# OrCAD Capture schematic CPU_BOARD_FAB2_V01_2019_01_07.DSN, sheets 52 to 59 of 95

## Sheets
52 032 BDX-DE POWER_2: size B
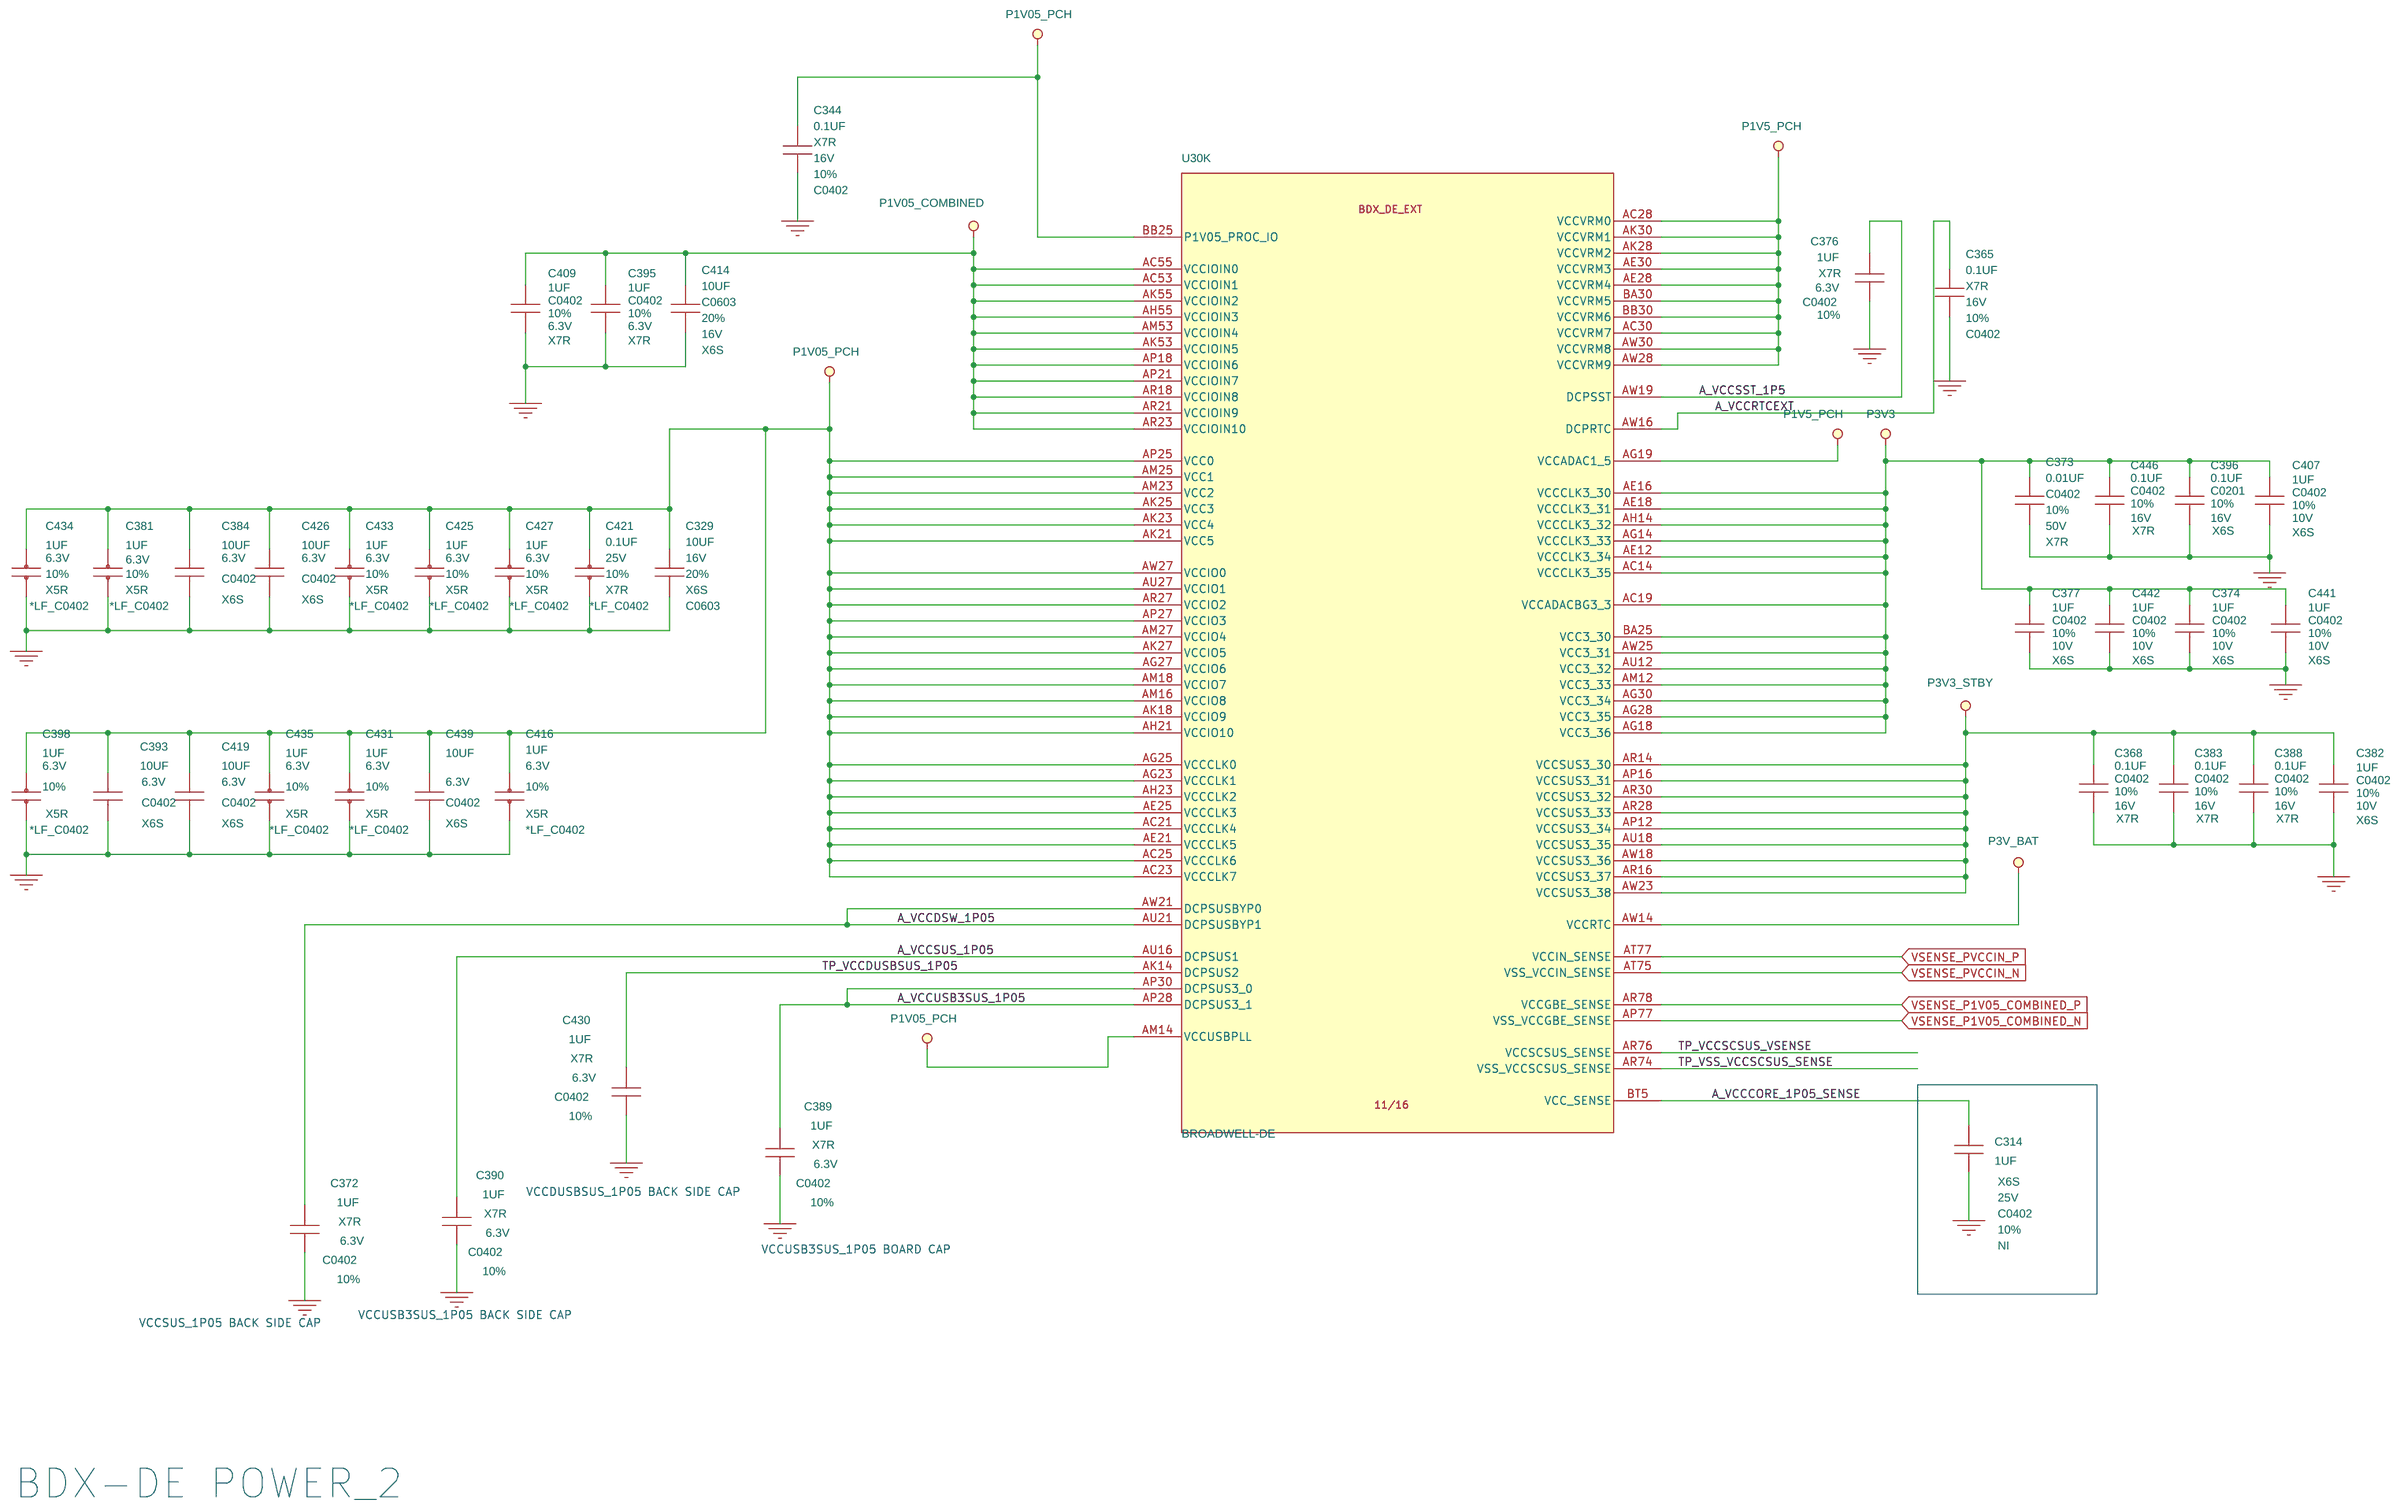
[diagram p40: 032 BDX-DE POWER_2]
53 033 BDX-DE GND_1: size B
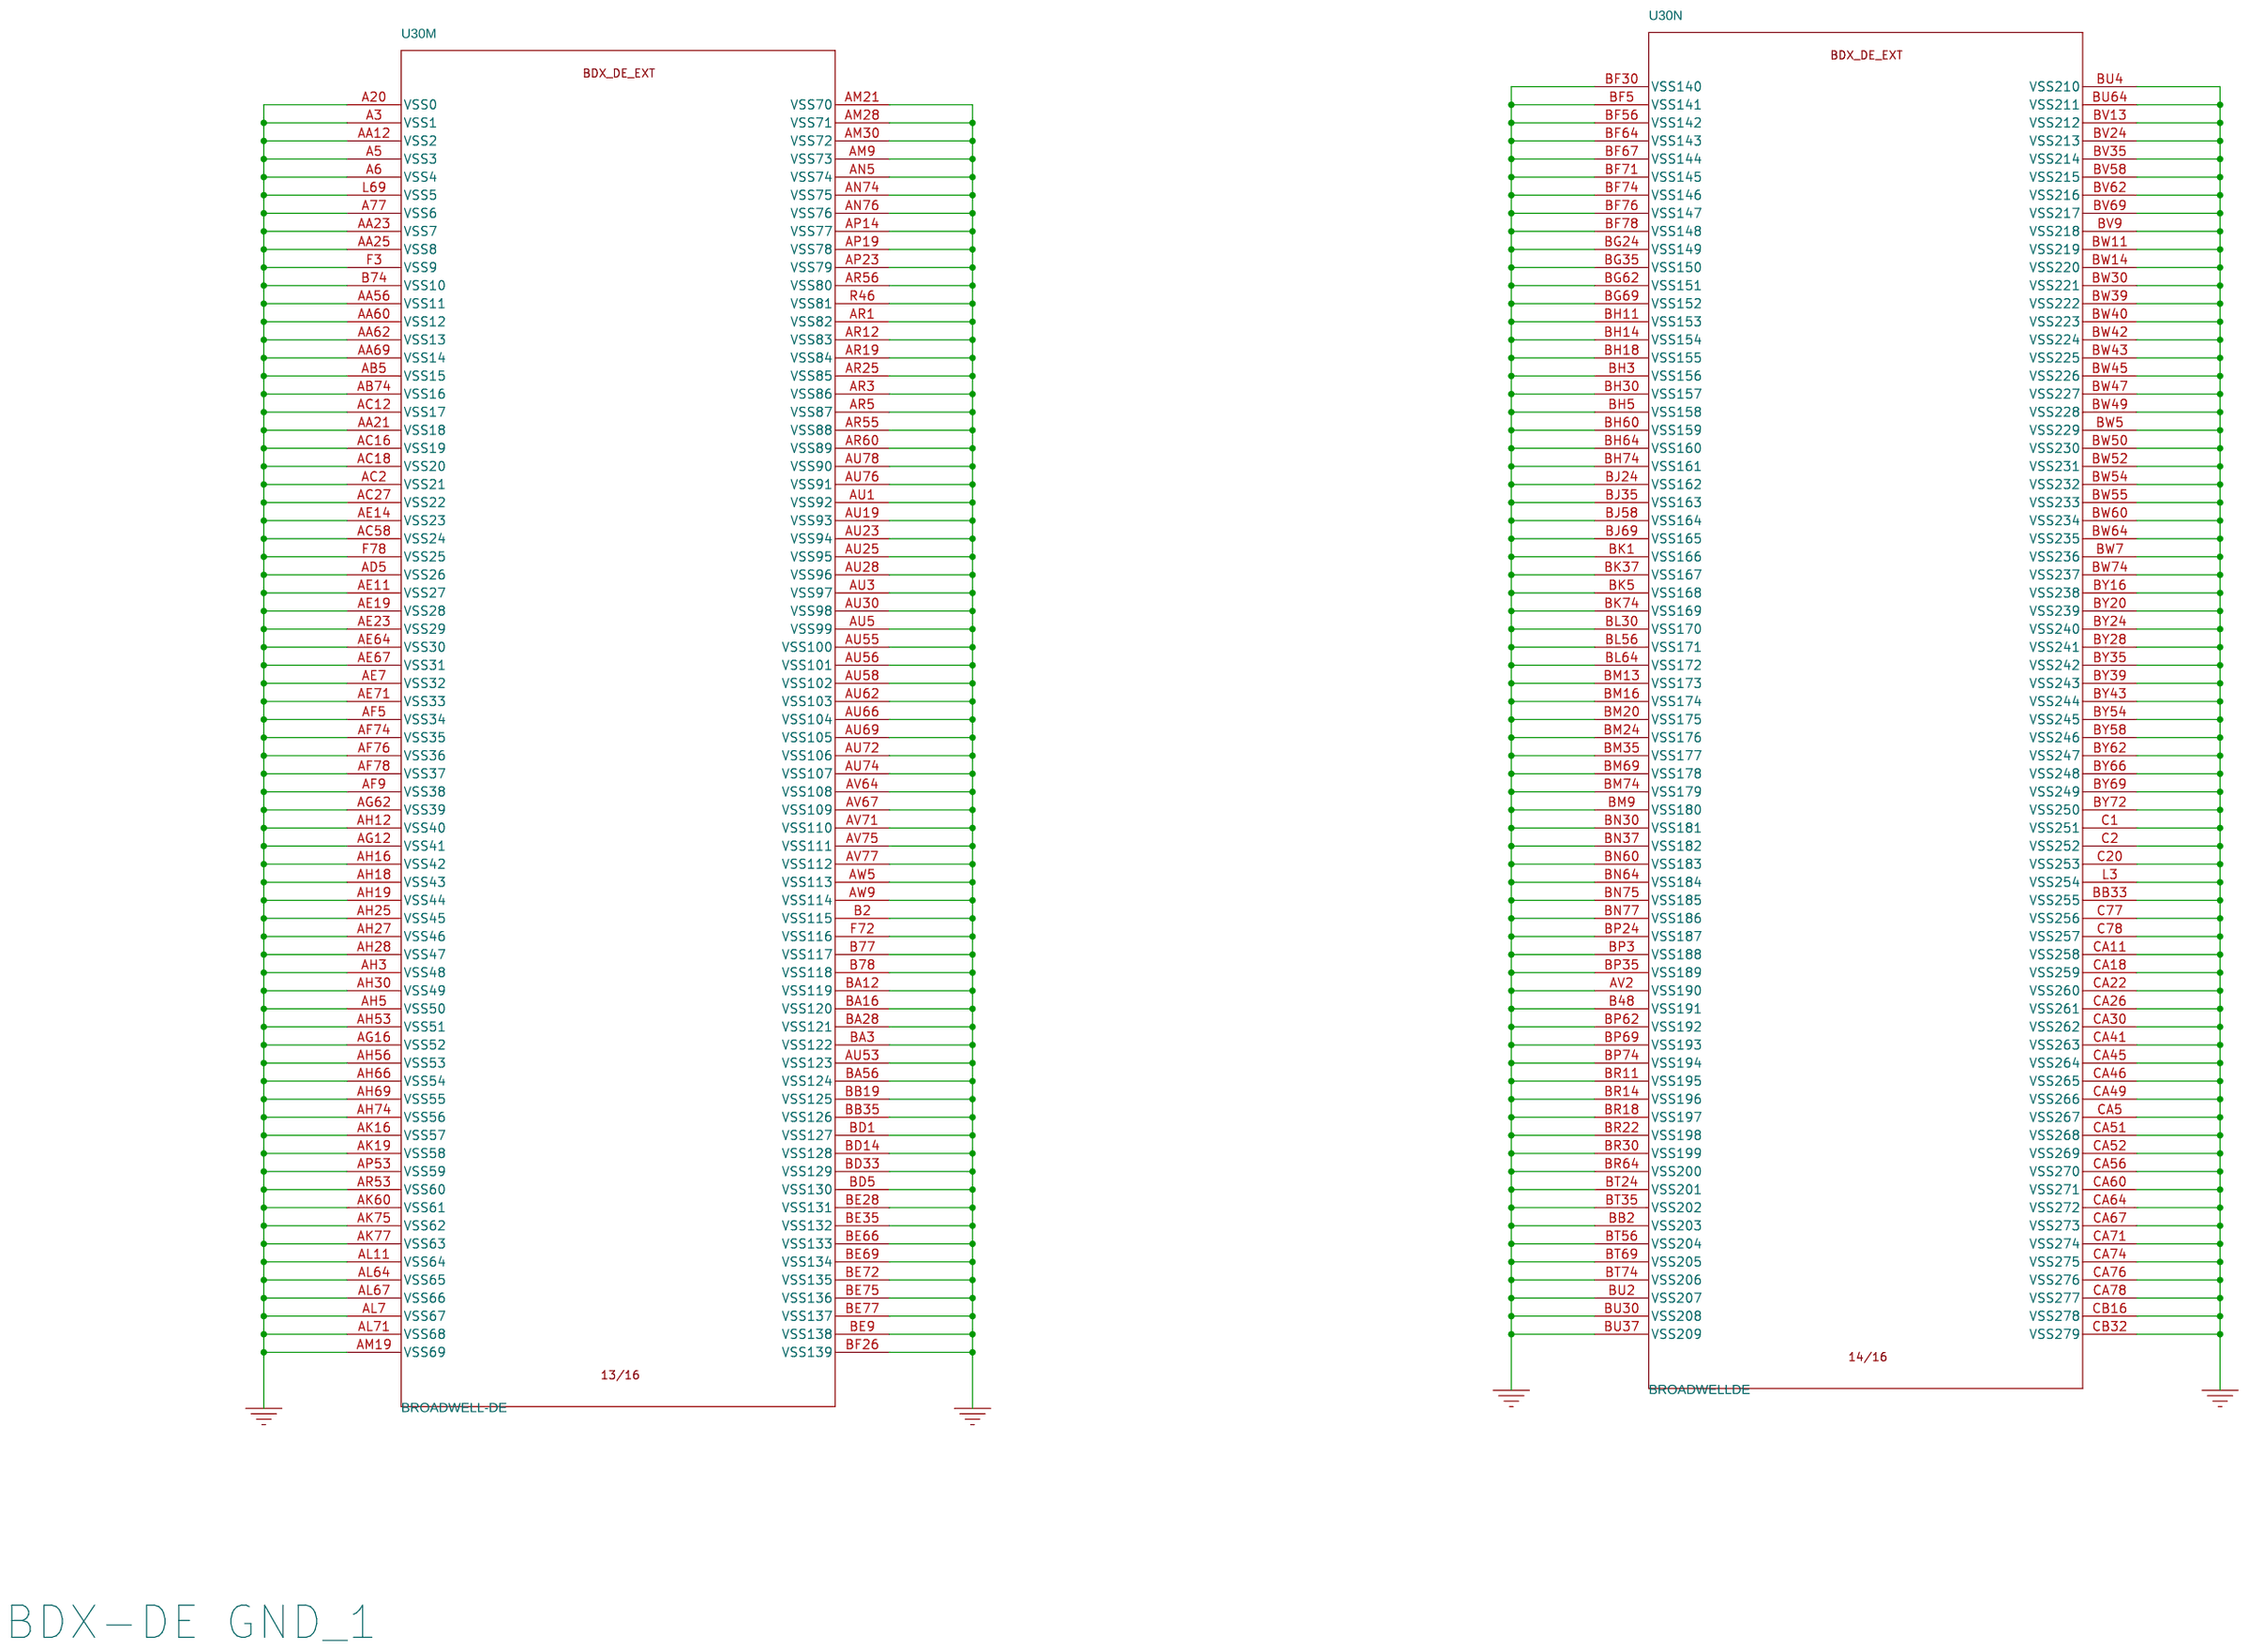
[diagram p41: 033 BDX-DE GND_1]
54 036 CPU XDP_1: size B
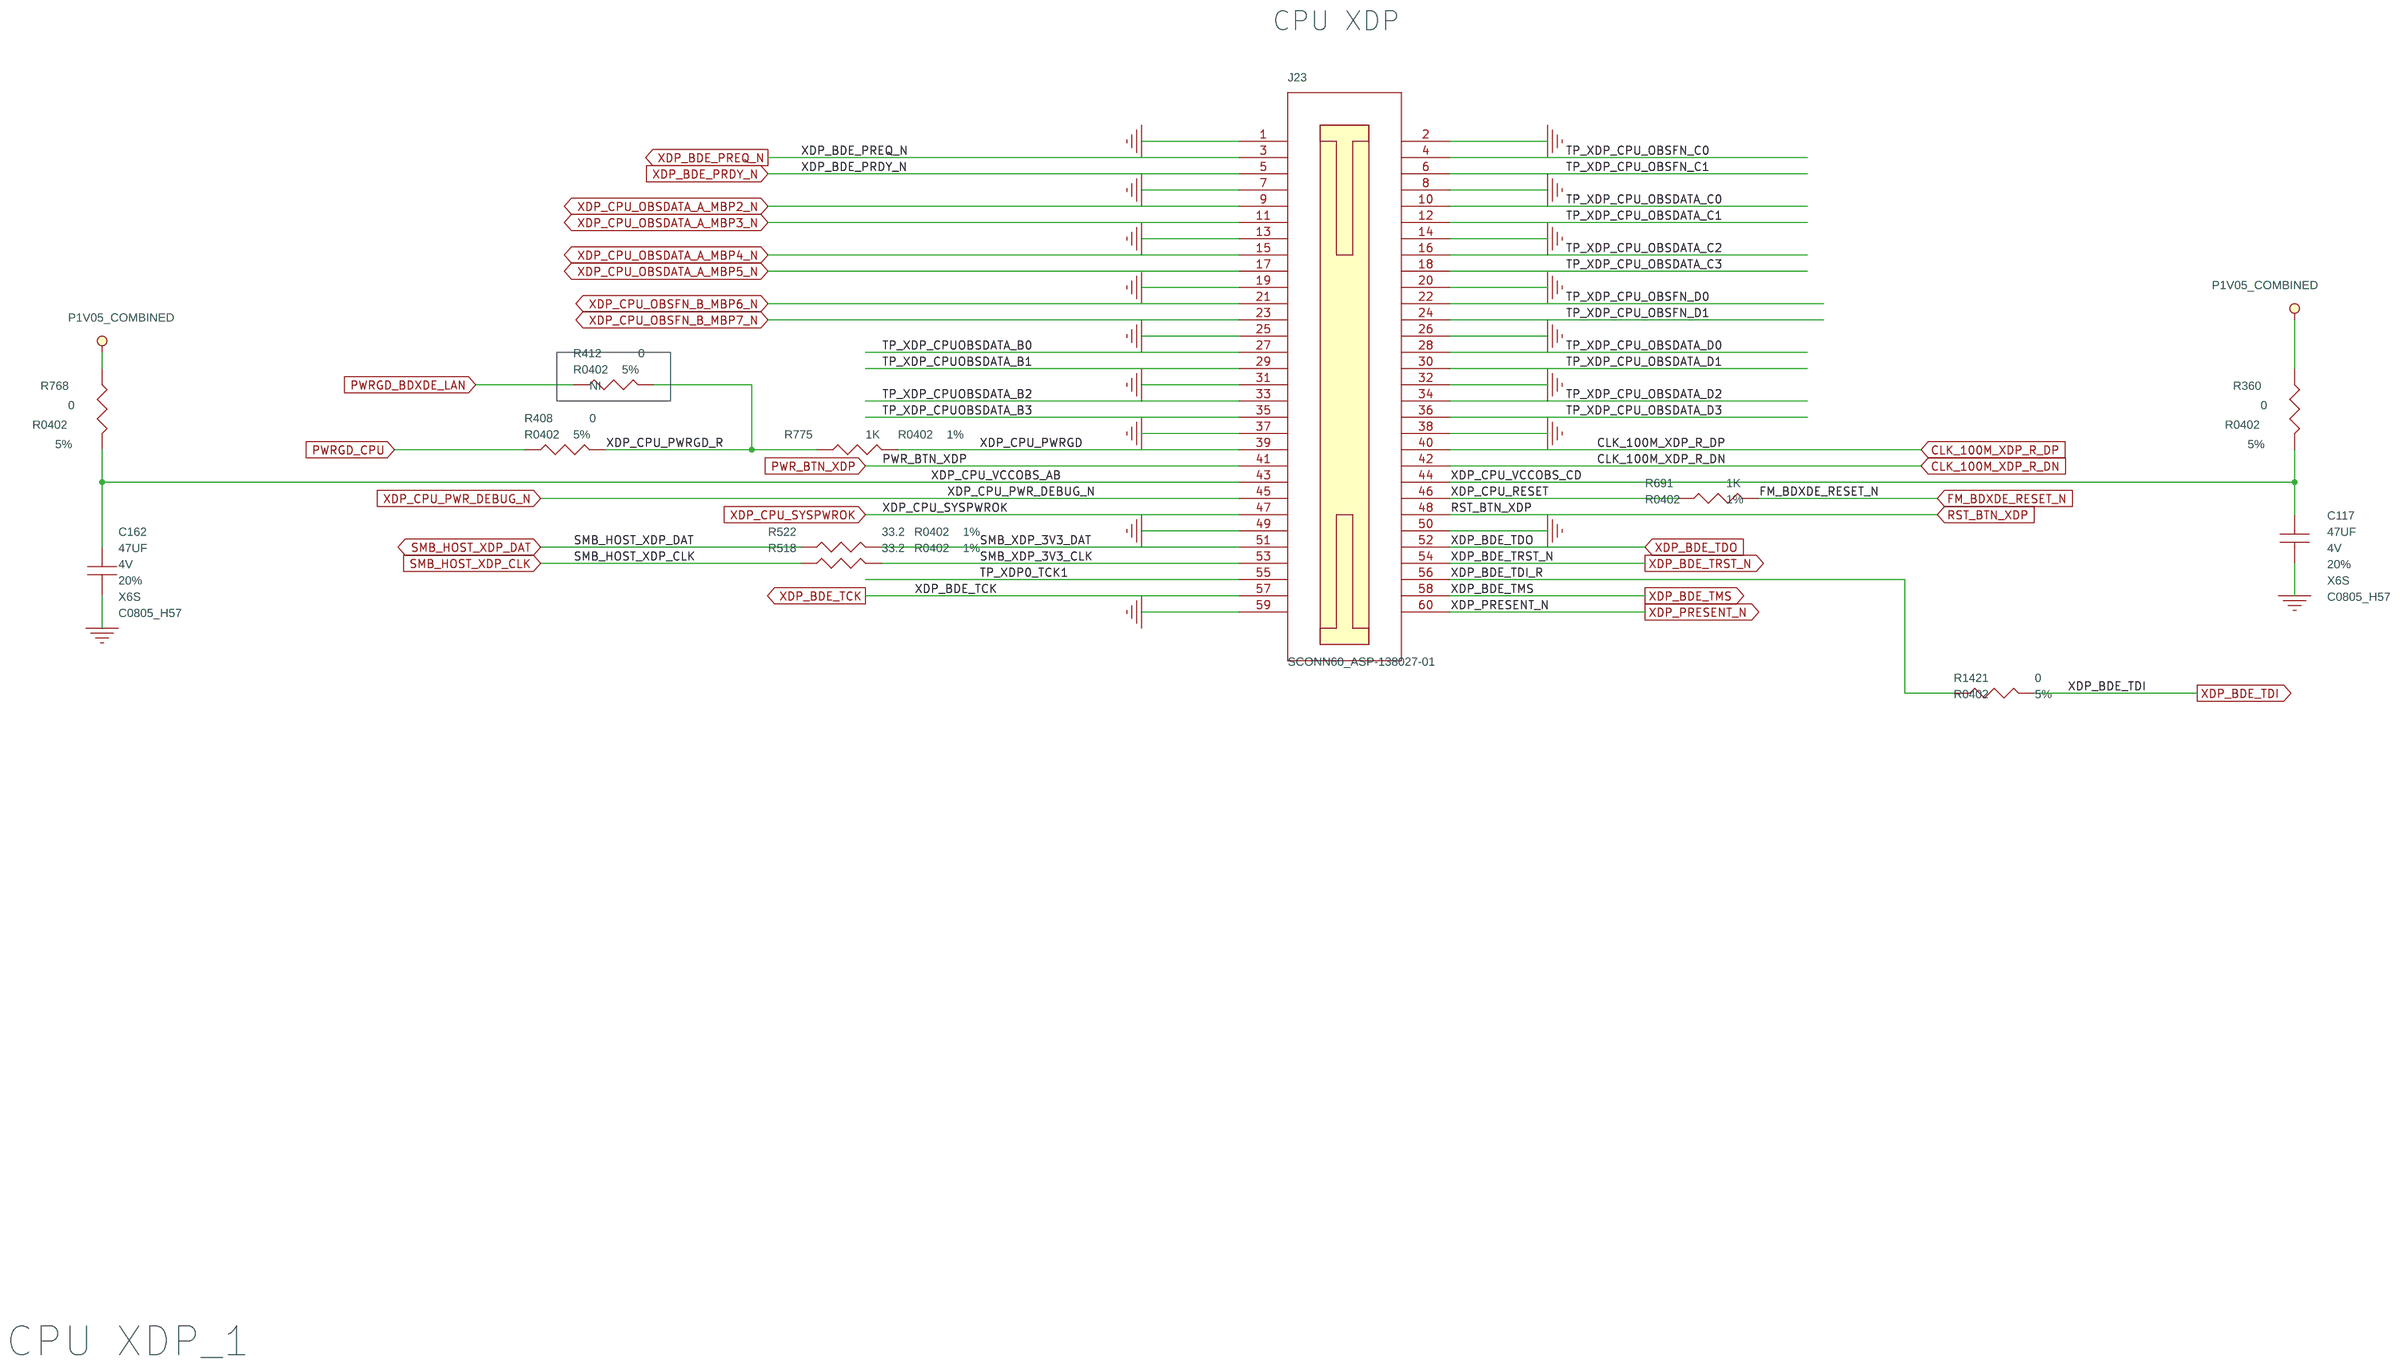
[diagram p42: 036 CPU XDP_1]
55 040 ERROR CNTL 1: size B
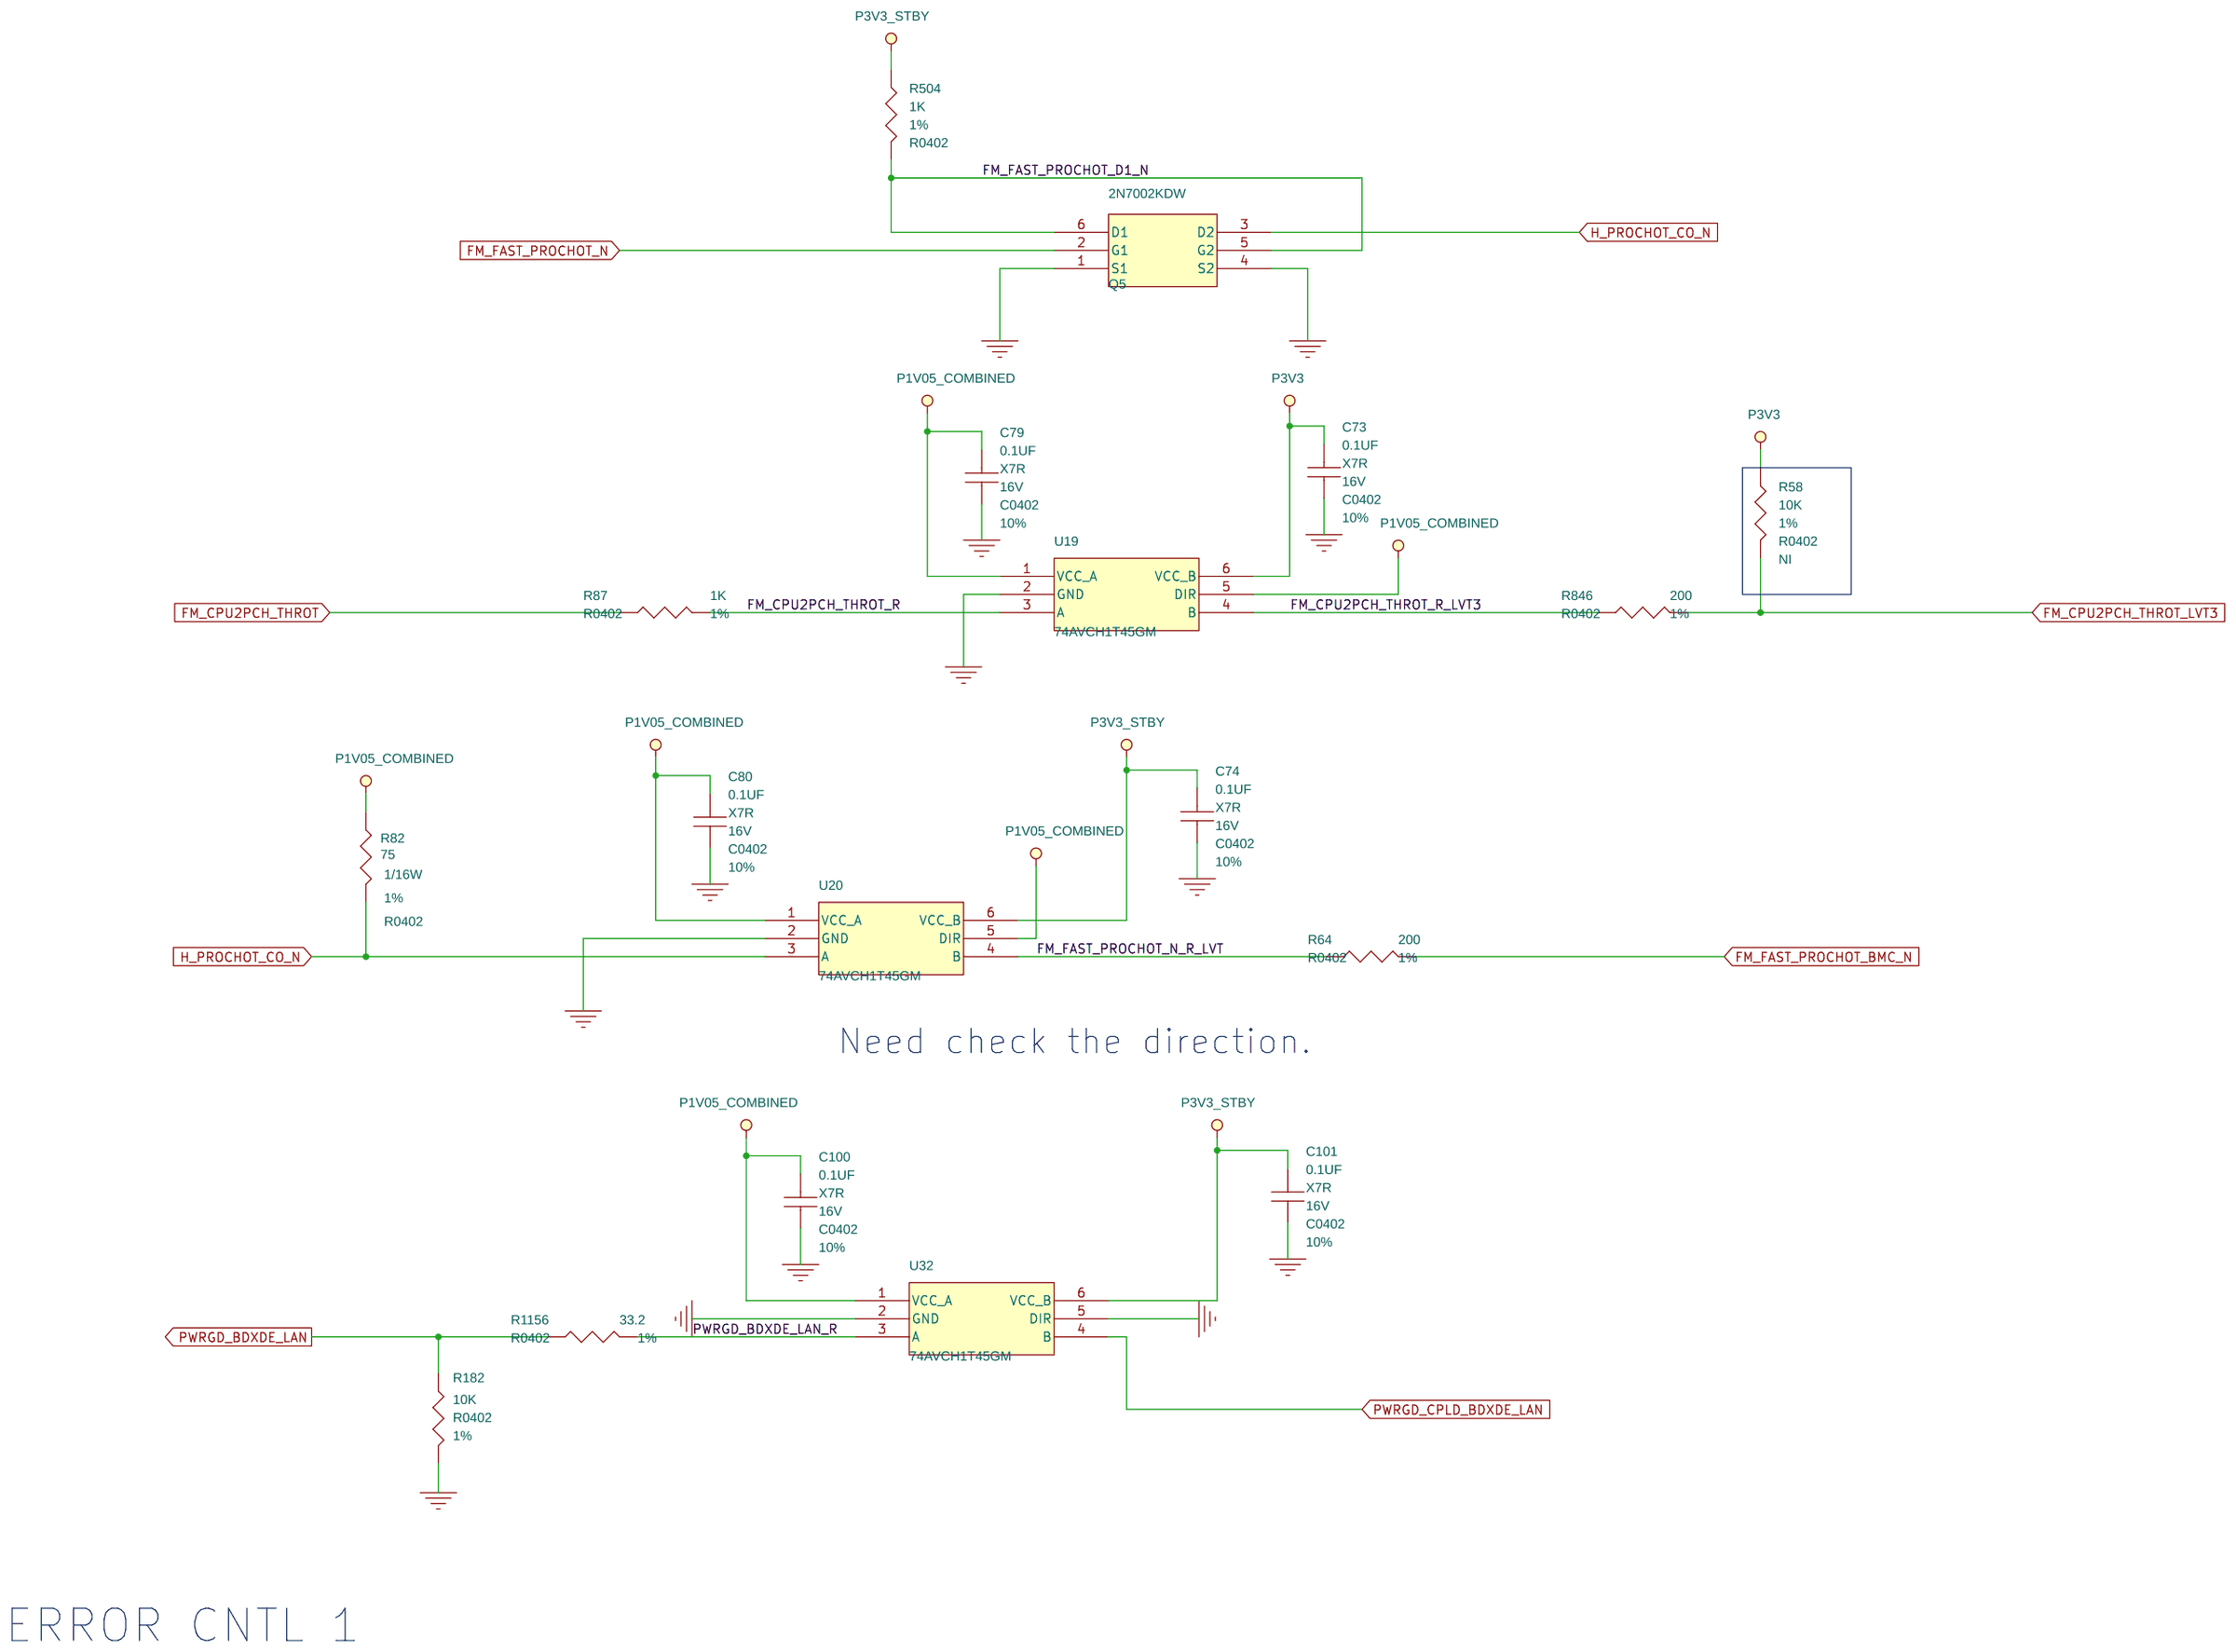
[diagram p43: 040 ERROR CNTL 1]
56 041 ERROR CNTL 2: size B
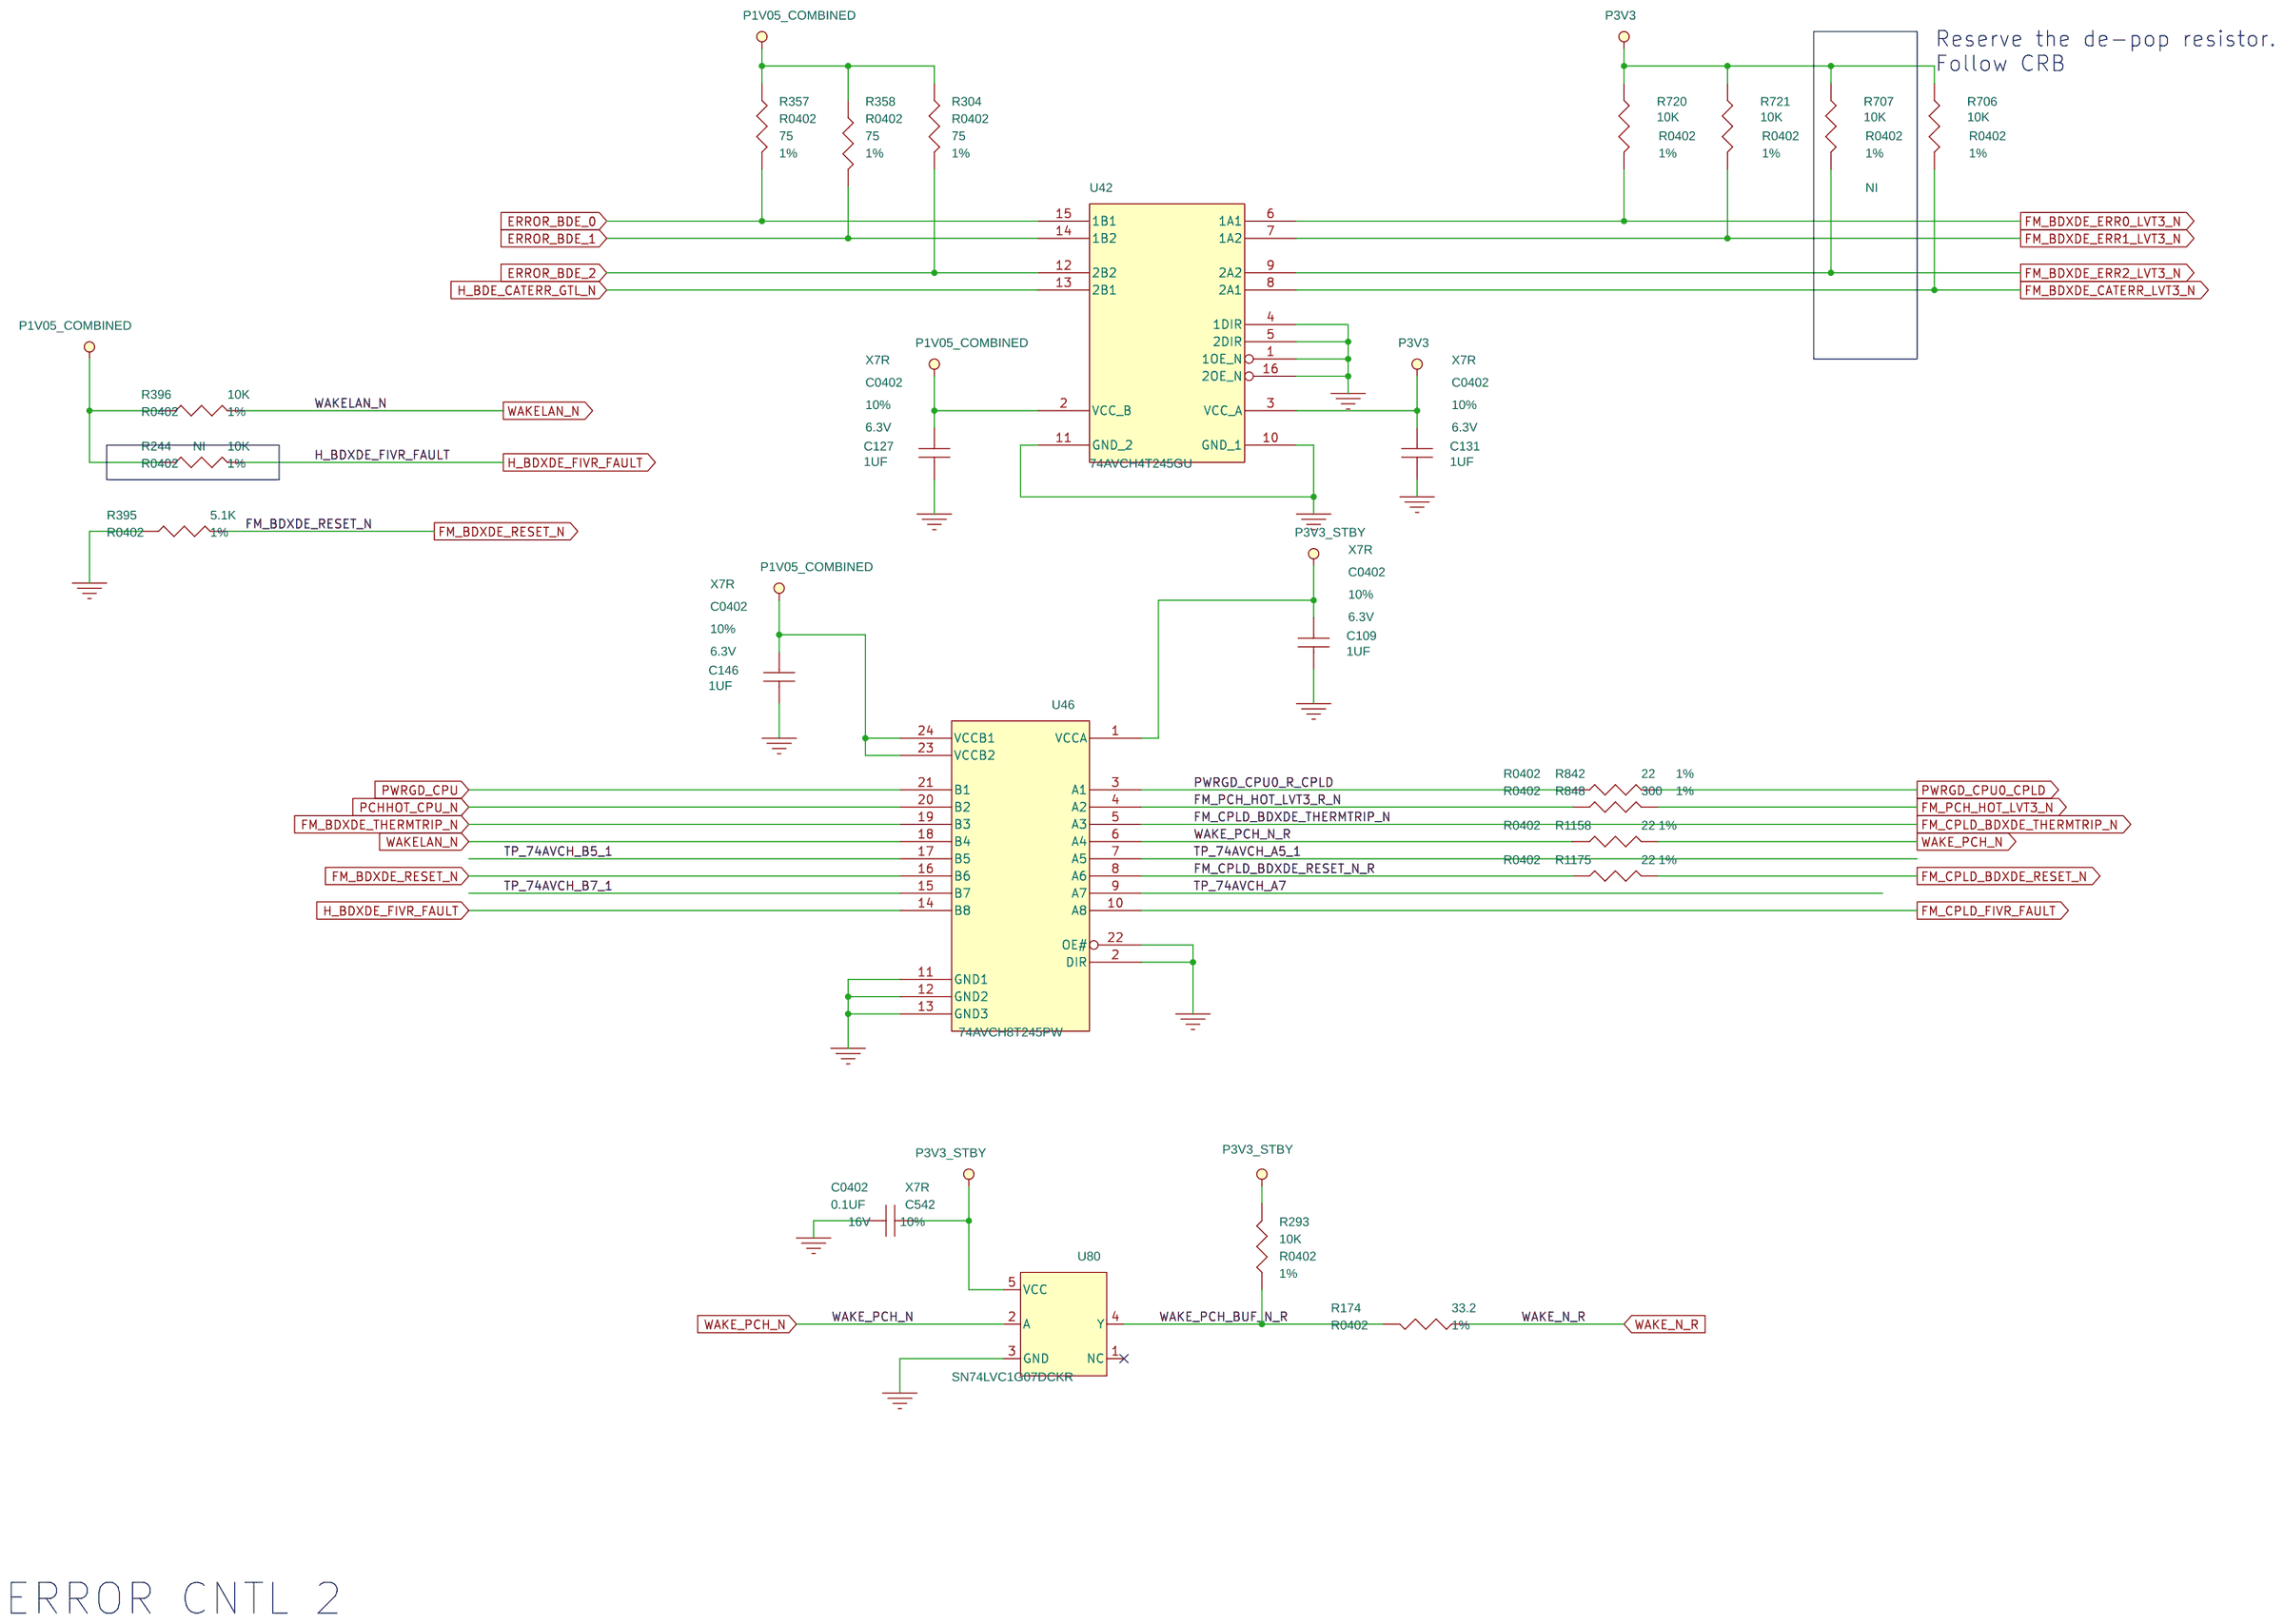
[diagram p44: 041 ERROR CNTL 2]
57 042 CPU SPI: size B
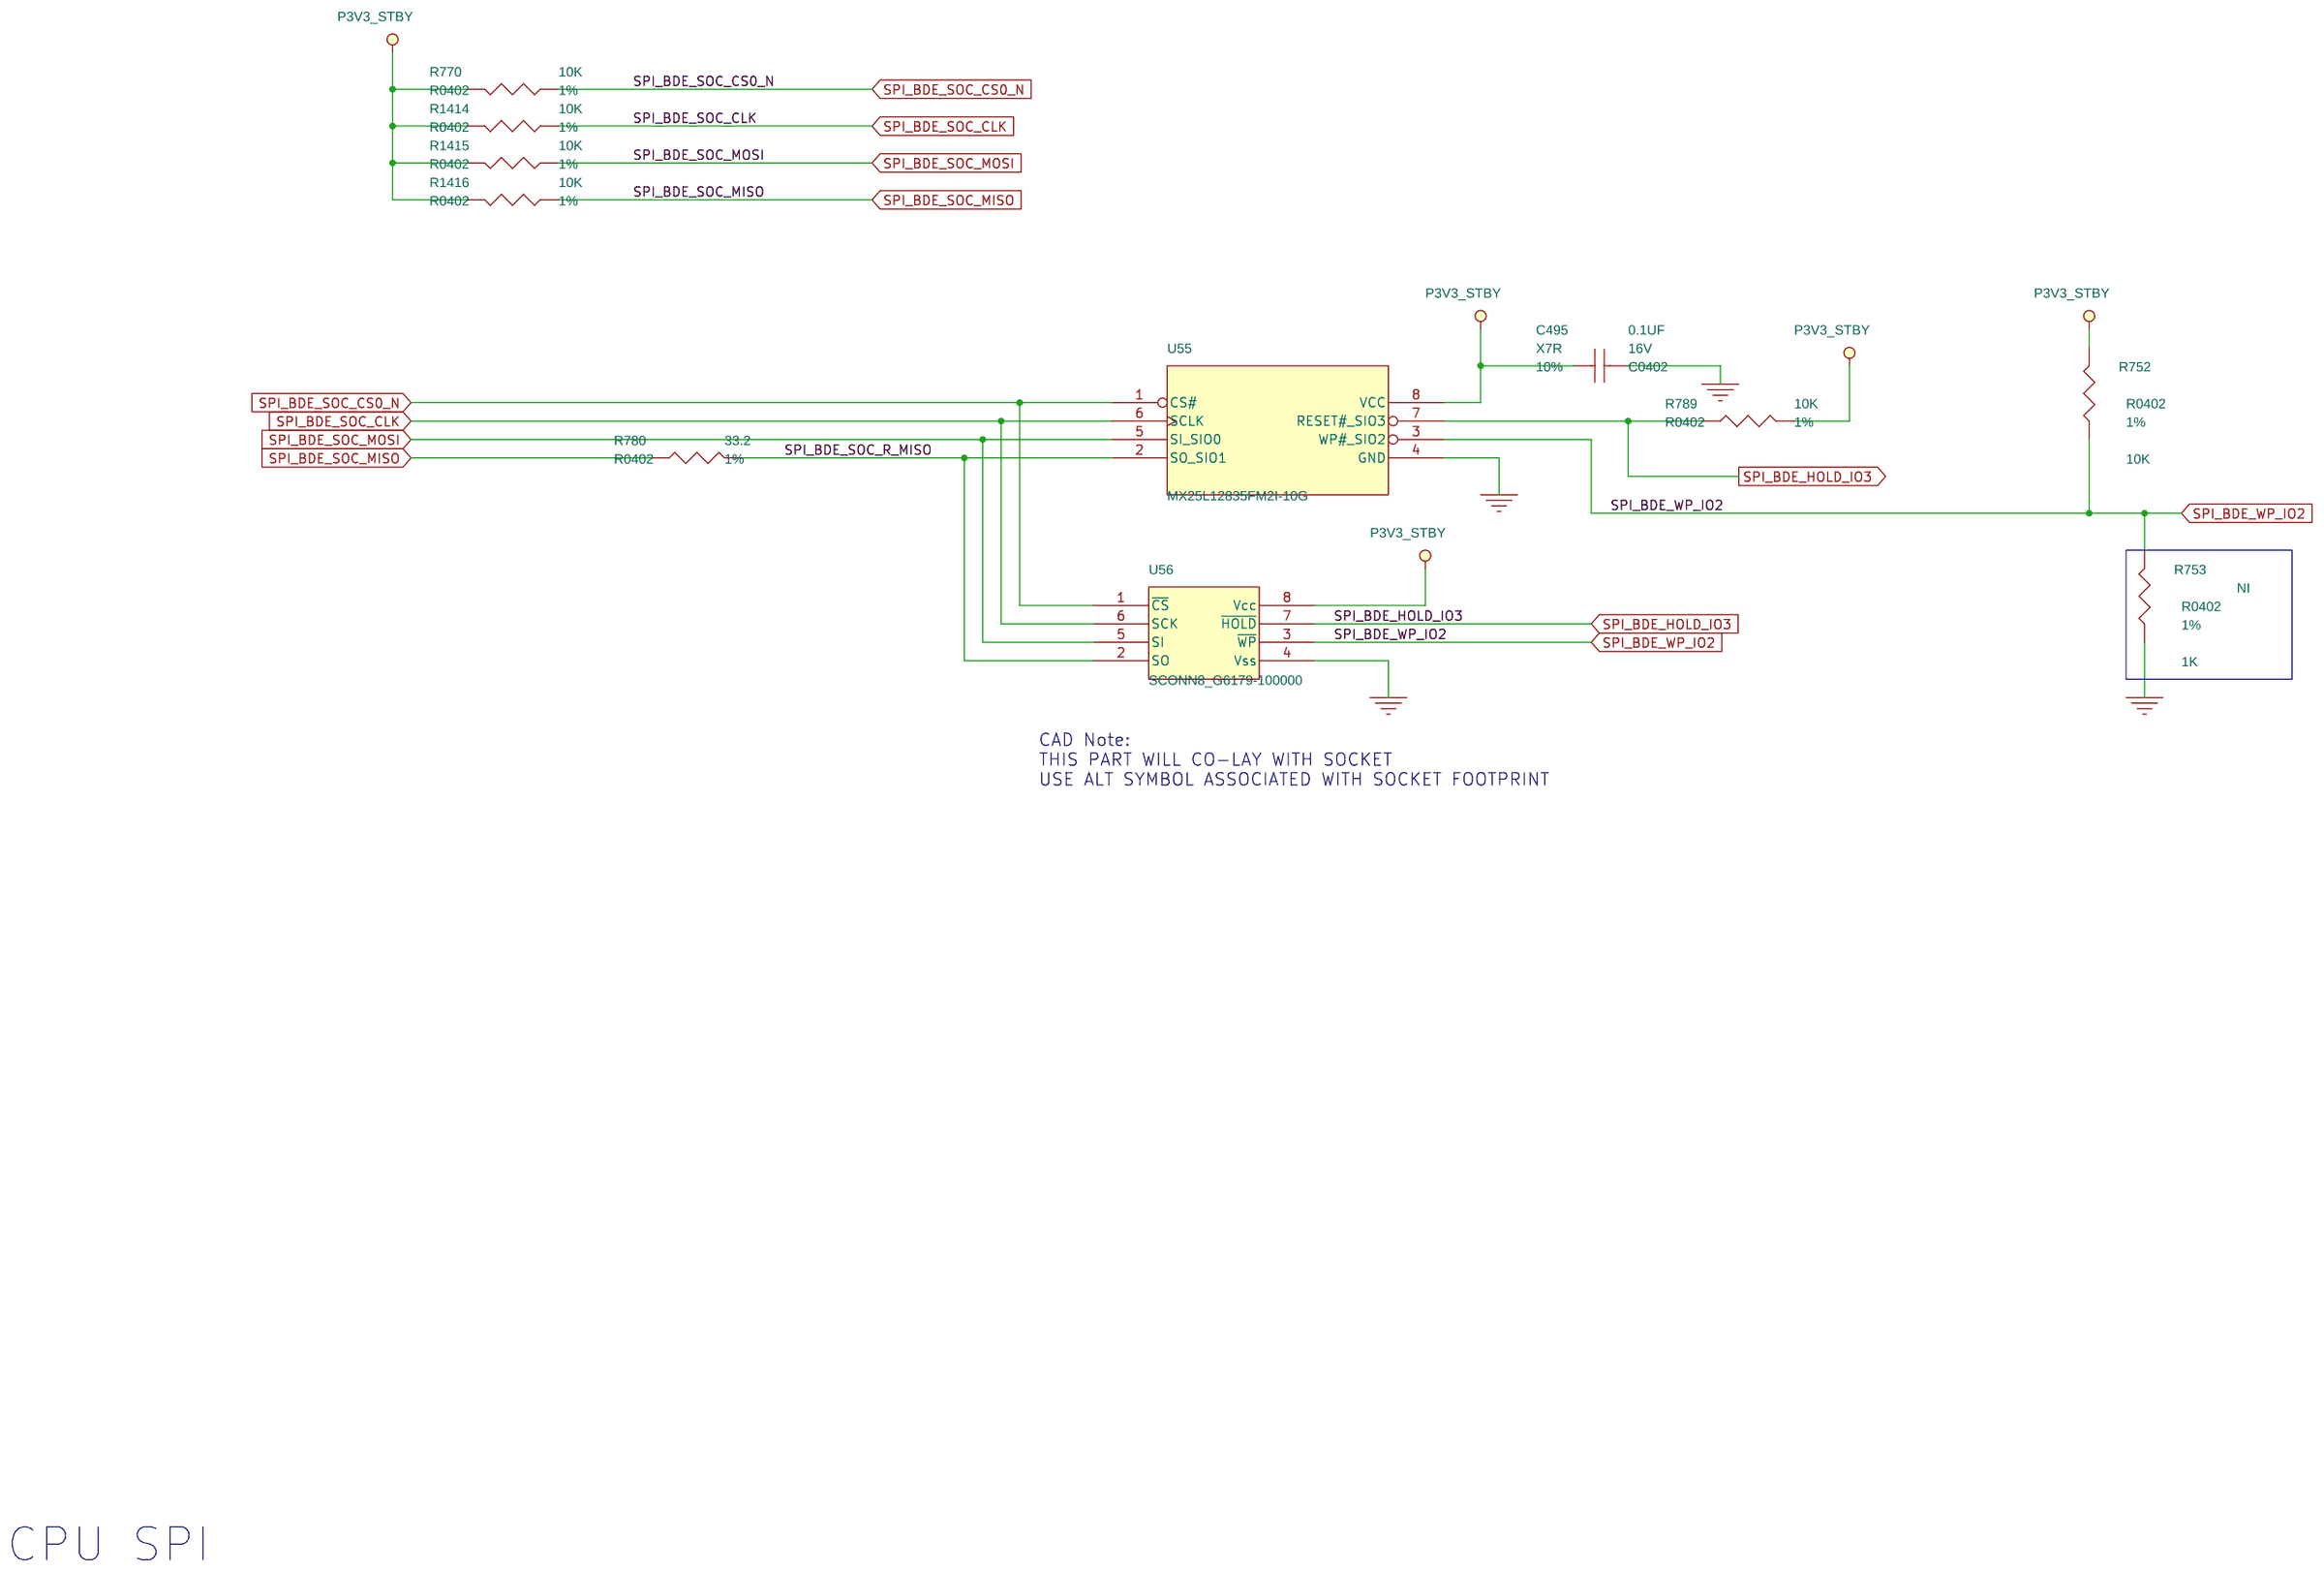
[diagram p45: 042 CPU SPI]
58 043 PLTRST_BUFFER: size B
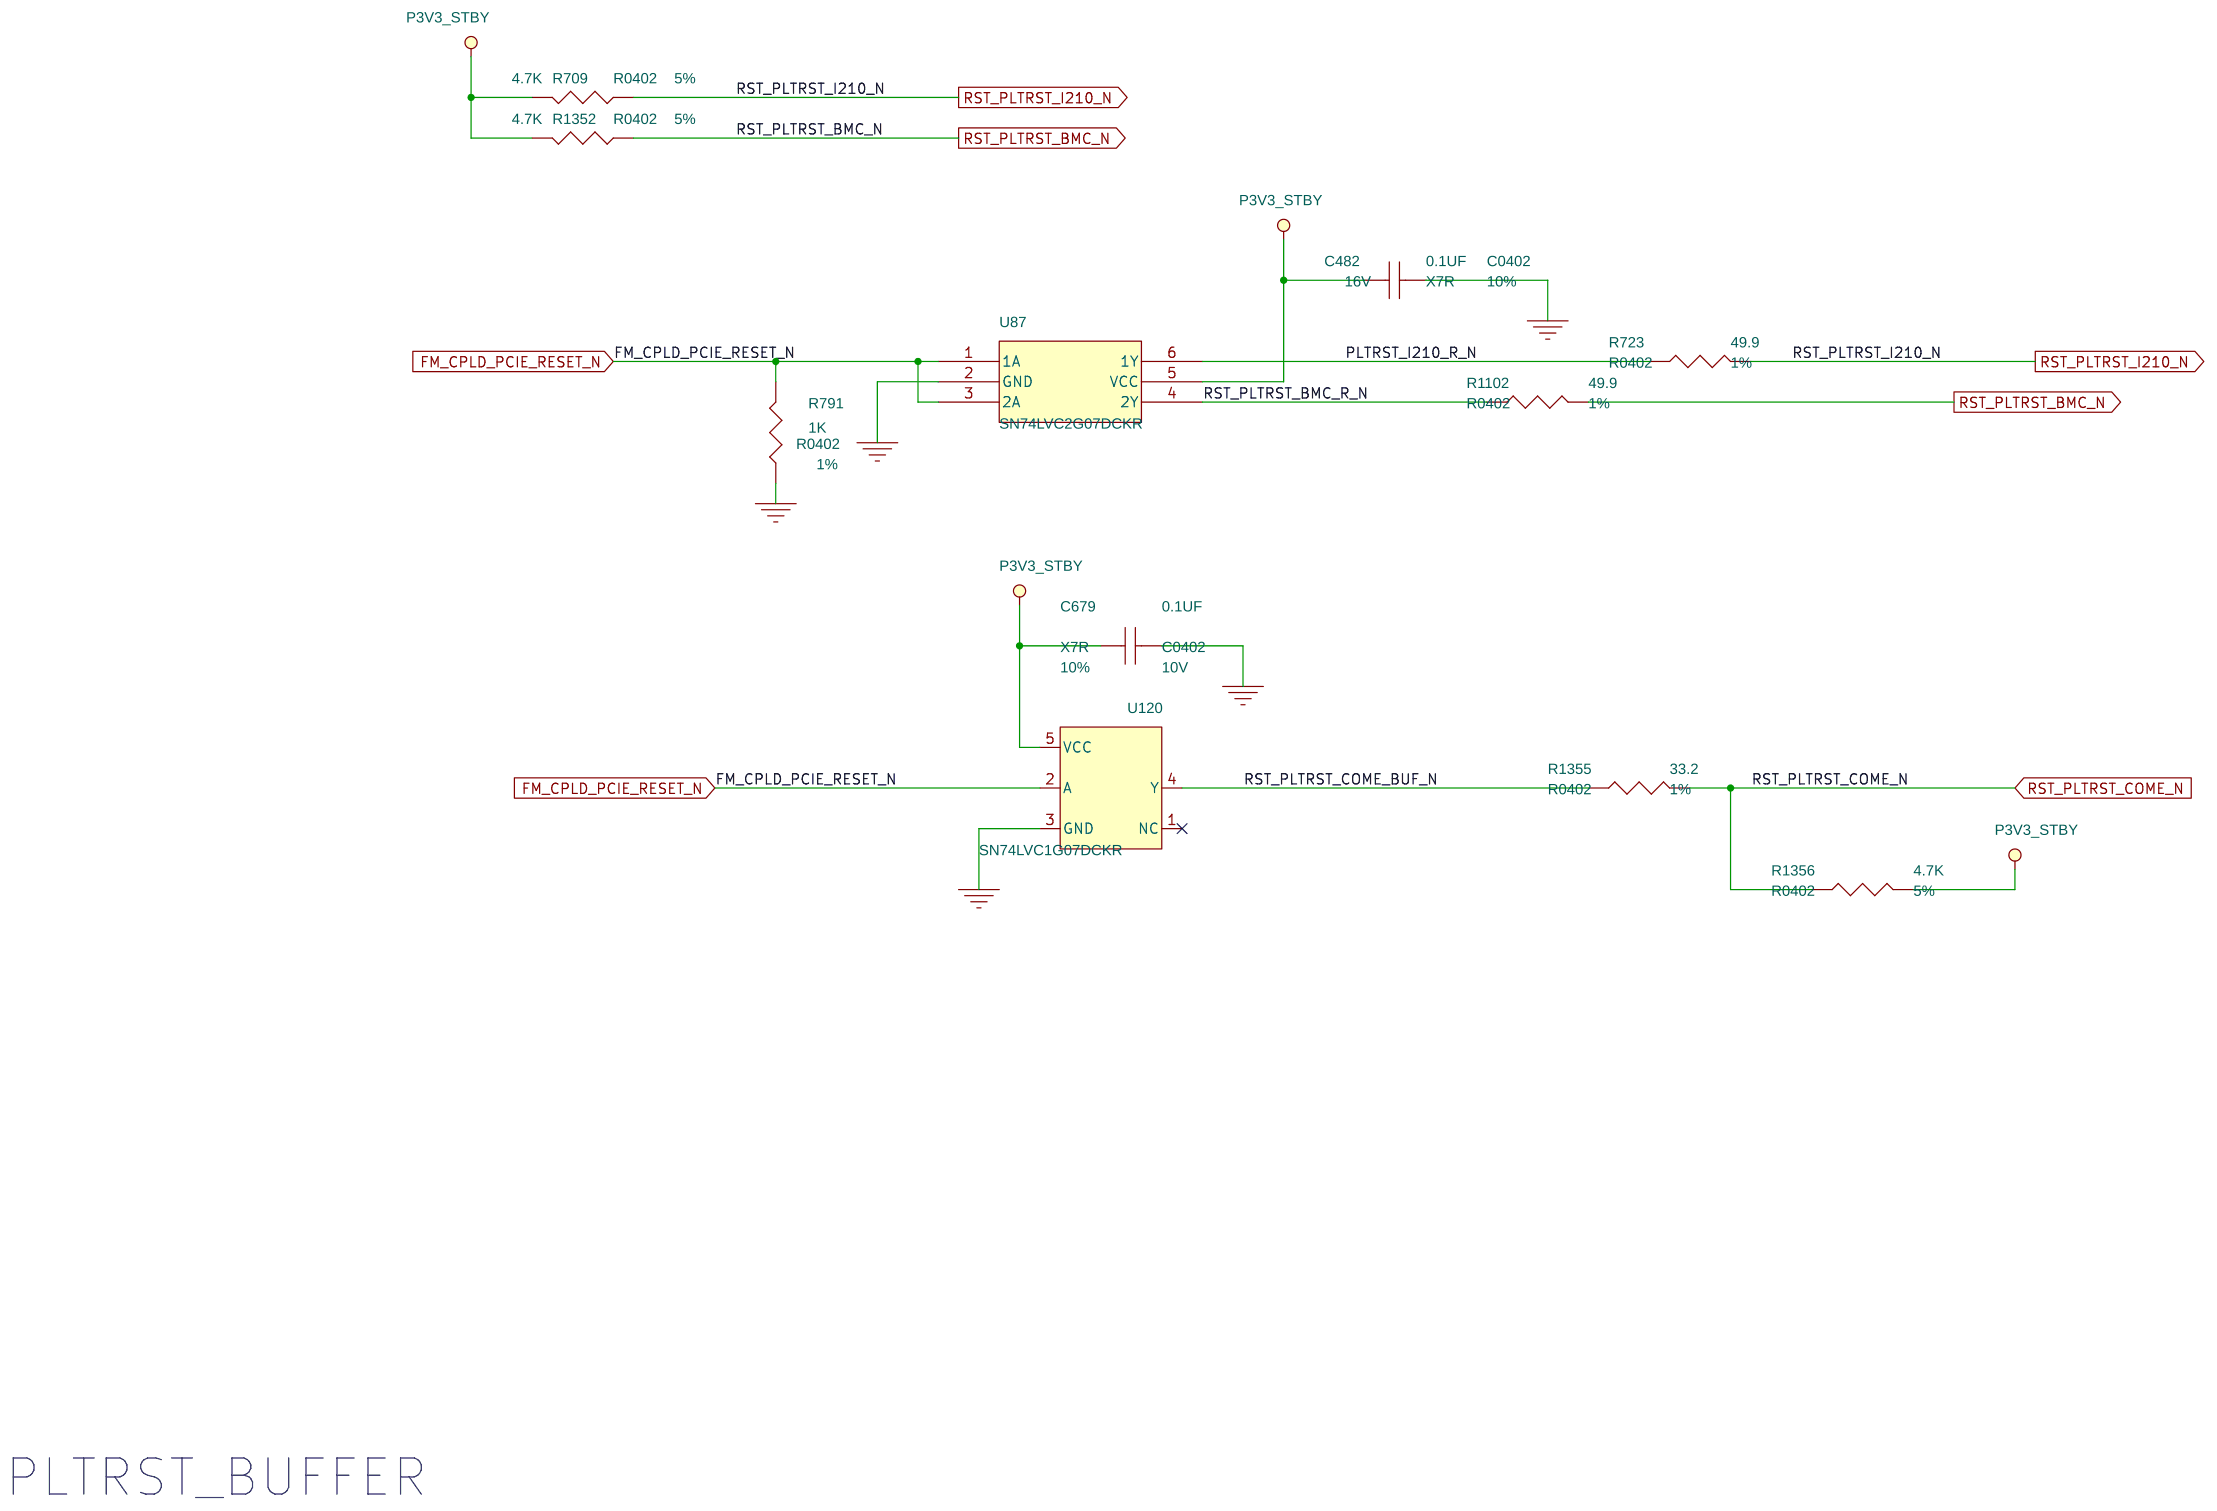
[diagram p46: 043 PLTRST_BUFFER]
59 044 SPI MUX: size B
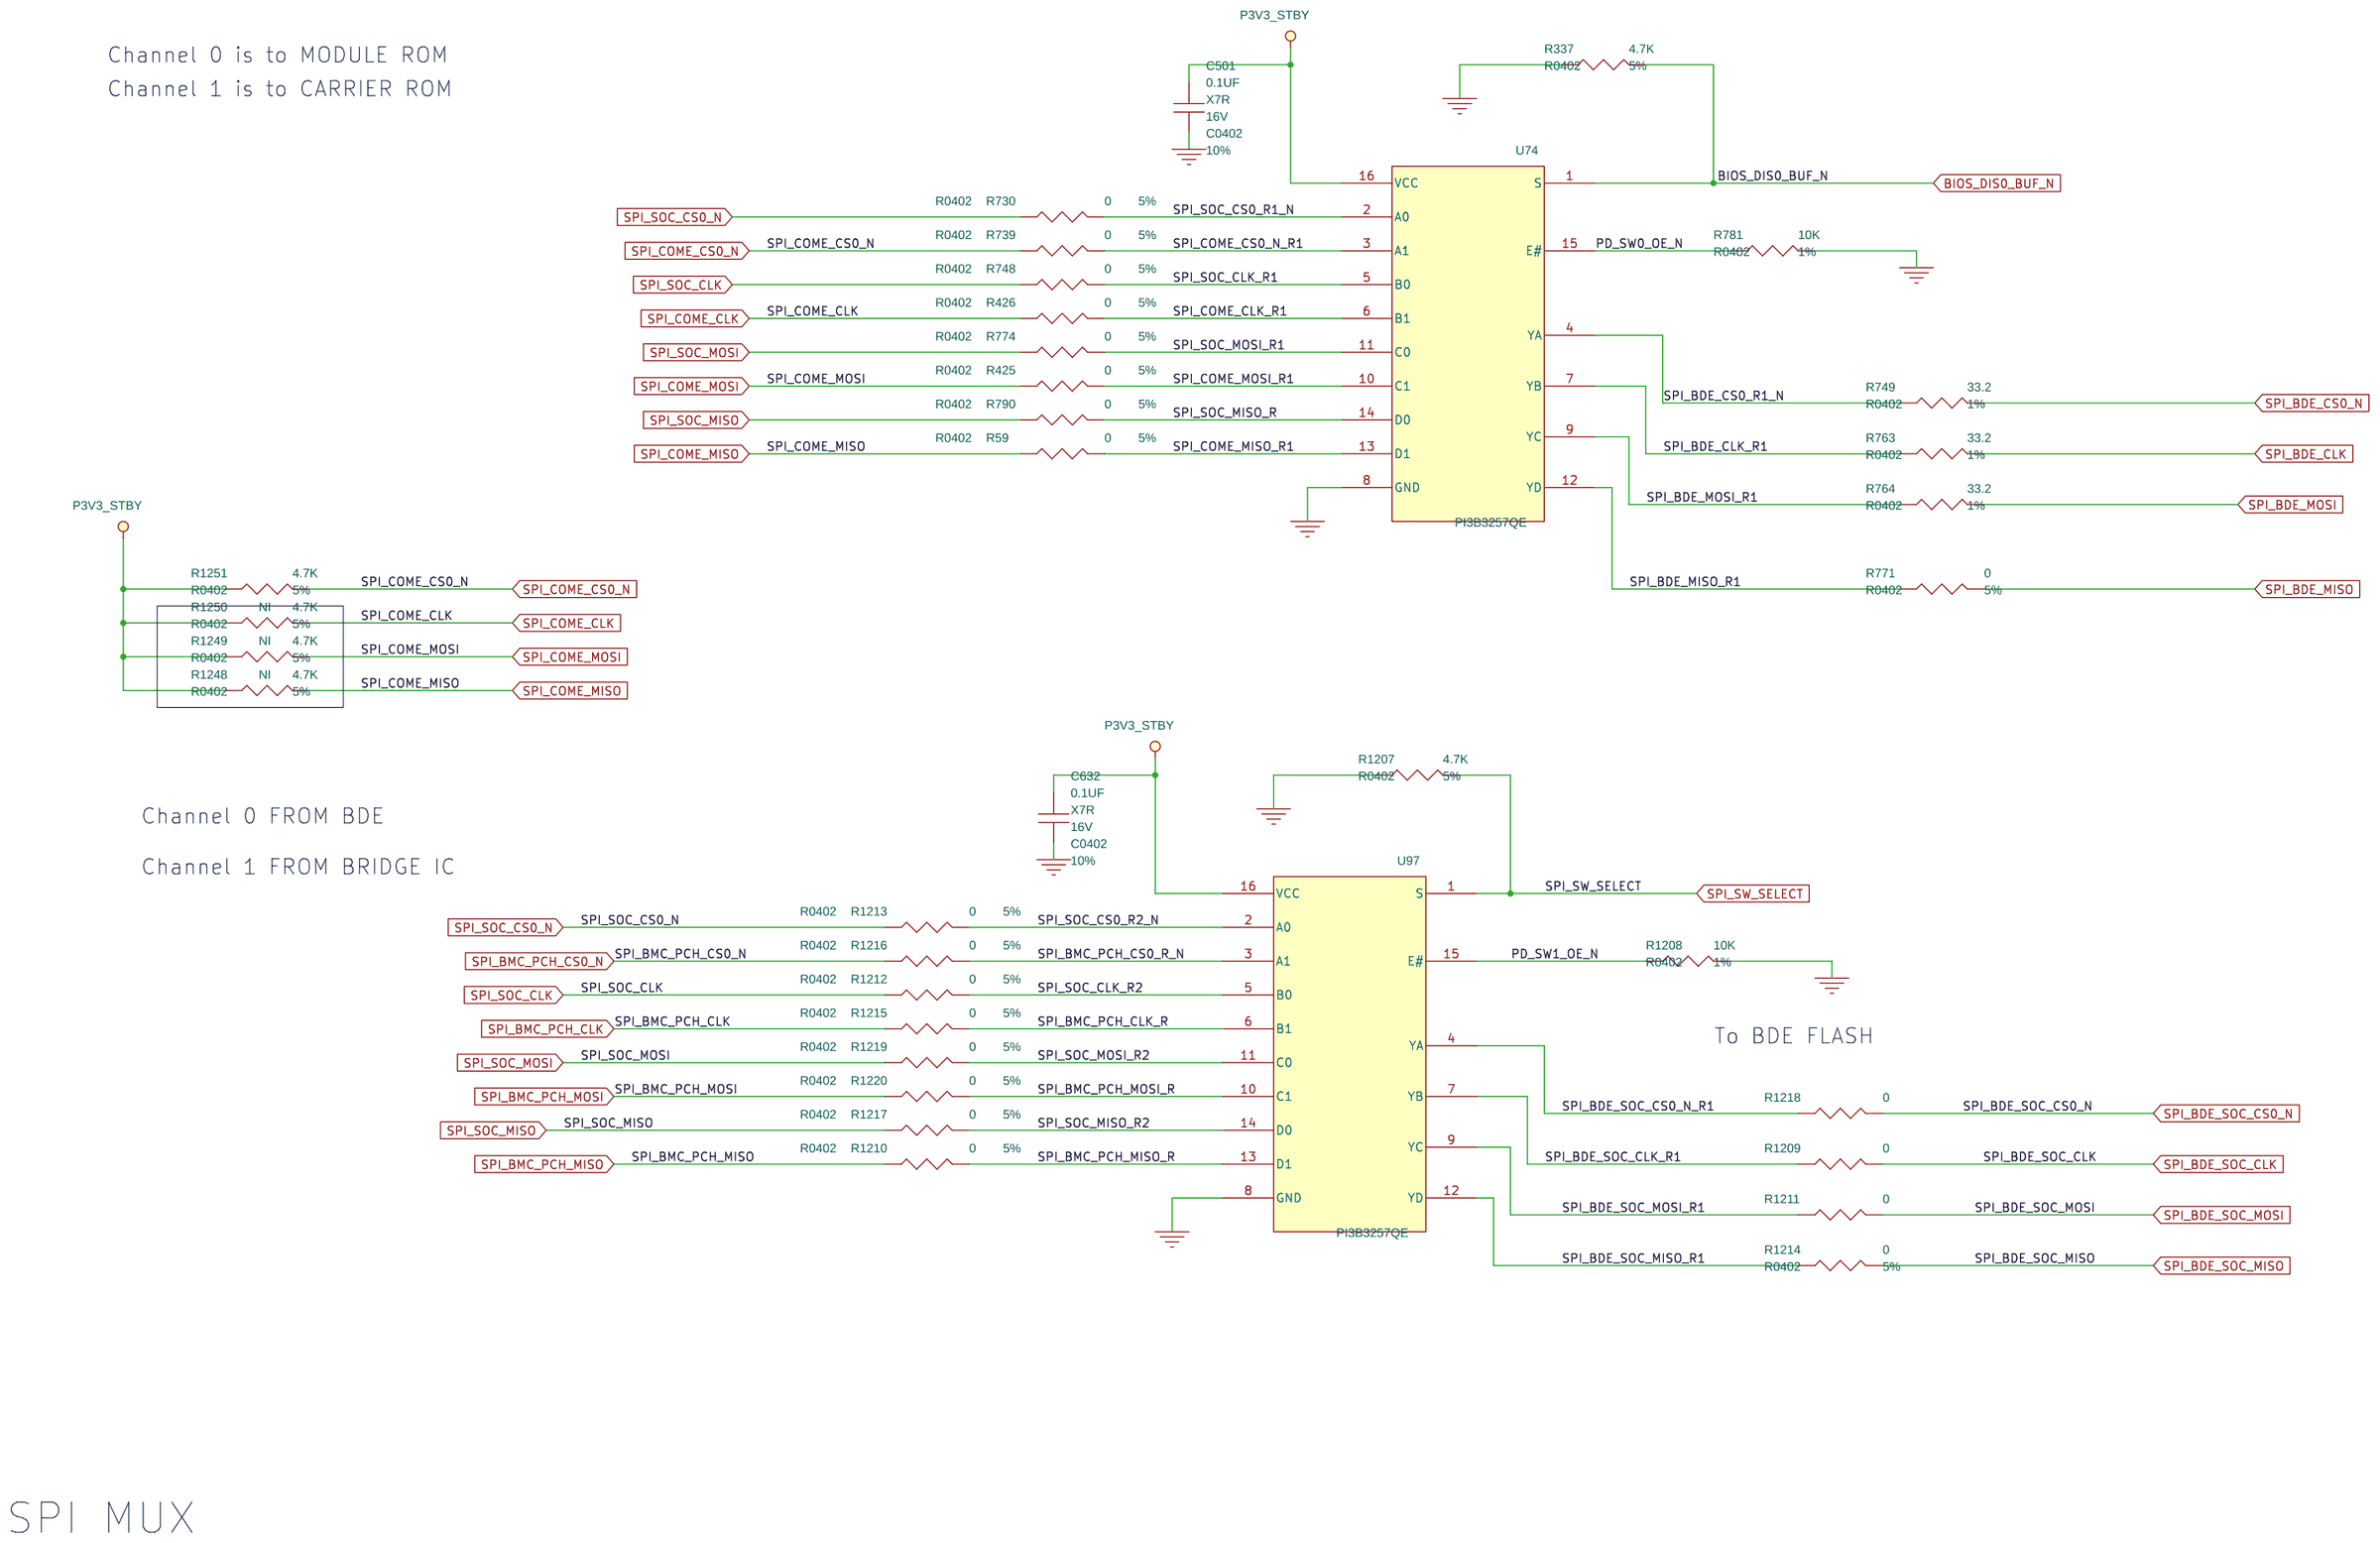
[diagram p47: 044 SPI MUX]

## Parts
sheet 023 BDX-DE SATA, USB2, USB3
U30  BROADWELL-DE  [BGA1667]  (sections A,B,C,D,E,F,G,H,I,J,K,L,M,N,O,P)
sheet 032 BDX-DE POWER_2
C314  1UF  [C0402]
C329  10UF  [C0603]
C344  0.1UF  [C0402]
C365  0.1UF  [C0402]
C368  0.1UF  [C0402]
C372  1UF  [C0402]
C373  0.01UF  [C0402]
C374  1UF  [C0402]
C376  1UF  [C0402]
C377  1UF  [C0402]
C381  1UF  [C0402_SMDC25]
C382  1UF  [C0402]
C383  0.1UF  [C0402]
C384  10UF  [C0402]
C388  0.1UF  [C0402]
C389  1UF  [C0402]
C390  1UF  [C0402]
C393  10UF  [C0402]
C395  1UF  [C0402]
C396  0.1UF  [C0201]
C398  1UF  [C0402_SMDC25]
C407  1UF  [C0402]
C409  1UF  [C0402]
C414  10UF  [C0603]
C416  1UF  [C0402_SMDC25]
C419  10UF  [C0402]
C421  0.1UF  [C0402_SMDC25]
C425  1UF  [C0402_SMDC25]
C426  10UF  [C0402]
C427  1UF  [C0402_SMDC25]
C430  1UF  [C0402]
C431  1UF  [C0402_SMDC25]
C433  1UF  [C0402_SMDC25]
C434  1UF  [C0402_SMDC25]
C435  1UF  [C0402_SMDC25]
C439  10UF  [C0402]
C441  1UF  [C0402]
C442  1UF  [C0402]
C446  0.1UF  [C0402]
sheet 036 CPU XDP_1
C117  47UF  [C0805_H57]
C162  47UF  [C0805_H57]
J23  SCONN60_ASP-138027-01  [CON_60S2H2D_P0-5W5-73_LDV]
R360  0  [R0402]
R408  0  [R0402]
R412  0  [R0402]
R518  33.2  [R0402]
R522  33.2  [R0402]
R691  1K  [R0402]
R768  0  [R0402]
R775  1K  [R0402]
R1421  0  [R0402]
sheet 040 ERROR CNTL 1
C73  0.1UF  [C0402]
C74  0.1UF  [C0402]
C79  0.1UF  [C0402]
C80  0.1UF  [C0402]
C100  0.1UF  [C0402]
C101  0.1UF  [C0402]
Q5  2N7002KDW  [SOT363XD]
R58  10K  [R0402]
R64  200  [R0402]
R82  75  [R0402]
R87  1K  [R0402]
R182  10K  [R0402]
R504  1K  [R0402]
R846  200  [R0402]
R1156  33.2  [R0402]
U19  74AVCH1T45GM  [SOT886]
U20  74AVCH1T45GM  [SOT886]
U32  74AVCH1T45GM  [SOT886]
sheet 041 ERROR CNTL 2
C109  1UF  [C0402]
C127  1UF  [C0402]
C131  1UF  [C0402]
C146  1UF  [C0402]
C542  0.1UF  [C0402]
R174  33.2  [R0402]
R244  10K  [R0402]
R293  10K  [R0402]
R304  75  [R0402]
R357  75  [R0402]
R358  75  [R0402]
R395  5.1K  [R0402]
R396  10K  [R0402]
R706  10K  [R0402]
R707  10K  [R0402]
R720  10K  [R0402]
R721  10K  [R0402]
R842  22  [R0402]
R848  300  [R0402]
R1158  22  [R0402]
R1175  22  [R0402]
U42  74AVCH4T245GU  [XQFN16]
U46  74AVCH8T245PW  [TSSOP24XB]
U80  SN74LVC1G07DCKR  [SC70-5XB]
sheet 042 CPU SPI
C495  0.1UF  [C0402]
R752  10K  [R0402]
R753  1K  [R0402]
R770  10K  [R0402]
R780  33.2  [R0402]
R789  10K  [R0402]
R1414  10K  [R0402]
R1415  10K  [R0402]
R1416  10K  [R0402]
U55  MX25L12835FM2I-10G  [SOP8_1-27_5-23X5-28XA]
U56  SCONN8_G6179-100000  [SOCKET8S]
sheet 043 PLTRST_BUFFER
C482  0.1UF  [C0402]
C679  0.1UF  [C0402]
R709  4.7K  [R0402]
R723  49.9  [R0402]
R791  1K  [R0402]
R1102  49.9  [R0402]
R1352  4.7K  [R0402]
R1355  33.2  [R0402]
R1356  4.7K  [R0402]
U87  SN74LVC2G07DCKR  [SC70-6]
U120  SN74LVC1G07DCKR  [SC70-5XB]
sheet 044 SPI MUX
C501  0.1UF  [C0402]
C632  0.1UF  [C0402]
R59  0  [R0402]
R337  4.7K  [R0402]
R425  0  [R0402]
R426  0  [R0402]
R730  0  [R0402]
R739  0  [R0402]
R748  0  [R0402]
R749  33.2  [R0402]
R763  33.2  [R0402]
R764  33.2  [R0402]
R771  0  [R0402]
R774  0  [R0402]
R781  10K  [R0402]
R790  0  [R0402]
R1207  4.7K  [R0402]
R1208  10K  [R0402]
R1209  0  [R0402]
R1210  0  [R0402]
R1211  0  [R0402]
R1212  0  [R0402]
R1213  0  [R0402]
R1214  0  [R0402]
R1215  0  [R0402]
R1216  0  [R0402]
R1217  0  [R0402]
R1218  0  [R0402]
R1219  0  [R0402]
R1220  0  [R0402]
R1248  4.7K  [R0402]
R1249  4.7K  [R0402]
R1250  4.7K  [R0402]
R1251  4.7K  [R0402]
U74  PI3B3257QE  [QSOP16]
U97  PI3B3257QE  [QSOP16]

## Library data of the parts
U30 = BROADWELLDE: CPU(1667P)Broadwell-DE (FCBGA); CLASS: IC; Data: INT_Broadwell-DE_REV0_75.pdf; From_pj: S1M-MANSON; MATERIAL: IC; Manuf_name: INTEGRATED DEVICE TECHNOLOGY,INC.; Manuftr: INT; Part_Type: Tmp; Color: Default; Location X-Coordinate: 0; Location Y-Coordinate: 0; Power Pins Visible: False; Primitive: DEFAULT
C314 = CAP_NP: CAP CHIP 1UF 25V(+-10%,X6S,0402); CLASS: DISCRETE; CMPLS_LVL: EP(V1); Data: MUR_GRM155R72A221KA01-01.pdf; From_pj: F06-RAYMOND; Lifecycle: Comp-Approve; MATERIAL: X6S; Manuf_PN: GRM155C81E105K; Manuf_name: MURATA ERIE N.A. INC TAIWAN BRANCH Okayama Murata Mfg.Co..Ltd.Wakura Murata Mfg.; Manufacturer: KYO; Manuftr: MUR; Not_insert: NI; Part_Type: *LF_C0402; RD_CMPLS_LVL: EP(V1); TOLERANCE: 10%; VOLTAGE: 25V; fp_ECN: 0402 SERIES_LL34.xls
C329 C414 = CAP_NP: CAP CHIP 10U 16V(+-20%,X6S,0603); CLASS: DISCRETE; CMPLS_LVL: EP(V1); Data: MUR_GRM188C81C106M.pdf; From_pj: JB9T-YUI-LIN; Lifecycle: Comp-Approve; MATERIAL: X6S; Manuf_PN: GRM188C81C106M; Manuf_name: MURATA ERIE N.A. INC TAIWAN BRANCH Okayama Murata Mfg.Co..Ltd. Wakura Murata Mfg; Manuftr: MUR; Part_Type: *LF_C0603; RD_CMPLS_LVL: EP(V1); TOLERANCE: 20%; VOLTAGE: 16V
C344 = CAP_NP: CAP CHIP 0.1U 16V(10%.X7R.0402); CLASS: DISCRETE; CMPLS_LVL: EP(V1); Data: MUR_LF_CAP SERIES_1.pdf; From_pj: S5A-TRAVIS; Lifecycle: Comp-Approve; MATERIAL: X7R; Manuf_PN: WBM155R71C104K; Manuf_name: MURATA ERIE N.A. INC TAIWAN BRANCH Okayama Murata Mfg.Co..Ltd. Wakura Murata Mfg; Manufacturer: MUR; Manuftr: MUR; Part_Type: *LF_C0402; RD_CMPLS_LVL: EP(V1); TOLERANCE: 10%; VOLTAGE: 16V; fp_ECN: 0402 SERIES_LL34.xls
C365 C542 = CAP_NP: CAP CHIP 0.1U 16V(10%.X7R.0402); CLASS: DISCRETE; CMPLS_LVL: EP(V1); Data: MUR_LF_CAP SERIES_1.pdf; From_pj: S5A-TRAVIS; Lifecycle: Comp-Approve; MATERIAL: X7R; Manuf_PN: WBM155R71C104K; Manuf_name: MURATA ERIE N.A. INC TAIWAN BRANCH Okayama Murata Mfg.Co..Ltd. Wakura Murata Mfg; Manufacturer: MUR; Manuftr: MUR; Part_Type: *LF_C0402; RD_CMPLS_LVL: EP(V1); TOLERANCE: 10%; VOLTAGE: 16V; fp_ECN: 0402 SERIES_LL34.xls; top_bot: TOP
C368 C383 C388 C446 = CAP_NP: CAP CHIP 0.1U 16V(10%.X7R.0402); CLASS: DISCRETE; CMPLS_LVL: EP(V1); Data: MUR_LF_CAP SERIES_1.pdf; From_pj: S5A-TRAVIS; Lifecycle: Comp-Approve; MATERIAL: X7R; Manuf_PN: WBM155R71C104K; Manuf_name: MURATA ERIE N.A. INC TAIWAN BRANCH Okayama Murata Mfg.Co..Ltd. Wakura Murata Mfg; Manuftr: MUR; Part_Type: *LF_C0402; RD_CMPLS_LVL: EP(V1); TOLERANCE: 10%; VOLTAGE: 16V; fp_ECN: 0402 SERIES_LL34.xls
C372 C376 C389 C390 C430 = CAP_NP: CAP CHIP 1U.6.3V(+-10%.X7R.0402); CLASS: DISCRETE; CMPLS_LVL: EP(V1); Data: MKP_LF_CAP SERIES.pdf; From_pj: T94-JEFF; Lifecycle: Comp-Approve; MATERIAL: X7R; Manuf_PN: MAG02X7R0J105K; Manuf_name: Matsuki Precision Ceramic Co.. Ltd.Matsuki Polymer Technology Co.. Ltd.; Manufacturer: KYO; Manuftr: MKP; Part_Type: *LF_C0402; RD_CMPLS_LVL: EP(V1); TOLERANCE: 10%; VOLTAGE: 6.3V; fp_ECN: 0402 SERIES_LL34.xls
C373 = CAP_NP: CAP CHIP 0.01U 50V(+-10%,X7R,0402); CLASS: DISCRETE; CMPLS_LVL: EP(V1); Data: MUR_MLCC_20110826.pdf; From_pj: T2B-CHEESE; Lifecycle: Comp-Approve; MATERIAL: X7R; Manuf_PN: WBM155R71H103K; Manuf_name: MURATA ERIE N.A. INC TAIWAN BRANCH Okayama Murata Mfg.Co.,Ltd.; Manuftr: MUR; Part_Type: *LF_C0402; RD_CMPLS_LVL: EP(V1); TOLERANCE: 10%; VOLTAGE: 50V; fp_ECN: 0402 SERIES_LL34.xls
C374 C377 C382 C407 C441 C442 = CAP_NP: CAP CHIP 1UF 10V(+-10%,X6S,0402); CLASS: DISCRETE; CMPLS_LVL: EP(V1); Data: MUR_LF_CAPSERIES_19JUN2012.pdf; From_pj: T6M-MARKCHEN; Lifecycle: Comp-Approve; MATERIAL: X6S; Manuf_PN: GRM155C81A105K; Manuf_name: MURATA ERIE N.A. INC TAIWAN BRANCH Okayama Murata Mfg.Co.,; Manuftr: MUR; Part_Type: *LF_C0402; RD_CMPLS_LVL: EP(V1); Standard: End of Design; TOLERANCE: 10%; VOLTAGE: 10V; fp_ECN: 0402 SERIES_LL34.xls
C381 C398 C416 C425 C427 C431 C433-C435 = CAP_NP_CIRCLEPAD: CAP CHIP 1U 6.3V(+-10%.X5R.0402)_FOR CIRCLE PAD; CLASS: DISCRETE; CMPLS_LVL: EP(V1); Data: AVX_SMCCP.pdf; From_pj: S2P-LOUISE; Lifecycle: Comp-Approve; MATERIAL: X5R; Manuf_PN: 04026D105KAT2A; Manuf_name: AVX CORPARATION CO.. LTD.; Manuftr: AVX; Part_Type: *LF_C0402; RD_CMPLS_LVL: EP(V1); Status: Preferred; TOLERANCE: 10%; VOLTAGE: 6.3V; fp_ECN: C0402_SMDC25.pdf
C384 C393 C419 C426 C439 = CAP_NP: CAP CHIP 10UF 6.3V(+-20%,X6S,0402); CLASS: DISCRETE; CMPLS_LVL: EP(V1); Data: MUR_GRM155C80J106M.pdf; From_pj: S4LA-MARK; Lifecycle: Comp-Approve; MATERIAL: X6S; Manuf_PN: GRM155C80J106M; Manuf_name: MURATA ERIE N.A. INC TAIWAN BRANCH Okayama Murata Mfg.Co.,; Manuftr: MUR; Part_Type: *LF_C0402; RD_CMPLS_LVL: EP(V1); TOLERANCE: 20%; VOLTAGE: 6.3V; fp_ECN: 0402 SERIES_LL34.xls
C109 C127 C131 C146 C395 C409 = CAP_NP: CAP CHIP 1U.6.3V(+-10%.X7R.0402); CLASS: DISCRETE; CMPLS_LVL: EP(V1); Data: MKP_LF_CAP SERIES.pdf; From_pj: T94-JEFF; Lifecycle: Comp-Approve; MATERIAL: X7R; Manuf_PN: MAG02X7R0J105K; Manuf_name: Matsuki Precision Ceramic Co.. Ltd.Matsuki Polymer Technology Co.. Ltd.; Manuftr: MKP; Part_Type: *LF_C0402; RD_CMPLS_LVL: EP(V1); TOLERANCE: 10%; VOLTAGE: 6.3V; fp_ECN: 0402 SERIES_LL34.xls
C396 = CAP_NP: CAP CHIP 0.1UF 16V(+-10%,X6S,0201); CLASS: DISCRETE; CMPLS_LVL: EP(V1); Data: TAY_EMK063AC6104KP.pdf; From_pj: S2P-SEAN; Lifecycle: Comp-Approve; MATERIAL: X6S; Manuf_PN: EMK063AC6104KP-F; Manuf_name: TAIYO YUDEN CO.,LTD; Manuftr: TAY; Part_Type: *LF_C0201; RD_CMPLS_LVL: EP(V1); TOLERANCE: 10%; VOLTAGE: 16V; fp_ECN: DCN-all 0201 RCL part.doc
C421 = CAP_NP_CIRCLEPAD: CAP CHIP 0.1U 25V(+-10%,X7R,0402)_FOR CIRCLE PAD; CLASS: DISCRETE; Data: YGO_CA-CC-SC SERIES.pdf; From_pj: T2R-ERIC; Lifecycle: Comp-Approve; MATERIAL: X7R; Manuf_PN: CC0402KRX7R8BB104; Manuf_name: YAGEO CORPORATION; Manuftr: YGO; Part_Type: *LF_C0402; RD_CMPLS_LVL: EP(V1); TOLERANCE: 10%; VOLTAGE: 25V; fp_ECN: C0402_SMDC25.pdf
C117 C162 = CAP_NP: CAP CHIP 47U 4V(+-20%.X6S.0805); CLASS: DISCRETE; CMPLS_LVL: EP(V1); Data: MUR_GRM21BC80G476M.pdf; From_pj: S2N-JUMP; Lifecycle: Comp-Approve; MATERIAL: X6S; Manuf_PN: GRM21BC80G476M; Manuf_name: MURATA ERIE N.A. INC TAIWAN BRANCH Okayama Murata Mfg.Co..Ltd.Wakura Murata Mfg.; Manuftr: MUR; Part_Type: *LF_C0805; RD_CMPLS_LVL: EP(V1); TOLERANCE: 20%; VOLTAGE: 4V
J23 = SCONN60_ASP13802701: CONN SMD HOUSING 60P 2R FS(P0.5,H3.25); CLASS: IO; CMPLS_LVL: EP(V1); Data: STC_ASP-138027-01.pdf; From_pj: S5G-BRIAN; Lifecycle: Comp-Approve; MATERIAL: IO; Manuf_PN: ASP-138027-01; Manuf_name: SAMTEC INC.; Manuftr: STC; Part_Type: *LF_Connector; RD_CMPLS_LVL: EP(V1); Standard: Non-Preferred
R360 R408 R730 R768 R771 R1209-R1214 R1217-R1219 R1421 = R: RESISTOR CHIP 0 1/16W +-5%(0402); CLASS: DISCRETE; CMPLS_LVL: EP; Data: WTC_LF_WR SERIES.pdf; Lifecycle: Comp-Approve; MATERIAL: CHIP; Manuf_PN: RR0510X-000-XN; Manuf_name: CYNTEC CO.. LTD.; Manuftr: CYN; Part_Type: *LF_Resistor; Status: Preferred; TOLERANCE: 5%; WATTAGE: 1/16W; fp_ECN: 0402 SERIES_LL34.xls
R412 = R: RESISTOR CHIP 0 1/16W +-5%(0402); CLASS: DISCRETE; CMPLS_LVL: EP; Data: WTC_LF_WR SERIES.pdf; Lifecycle: Comp-Approve; MATERIAL: CHIP; Manuf_PN: RR0510X-000-XN; Manuf_name: CYNTEC CO.. LTD.; Manuftr: CYN; Not_insert: NI; Part_Type: *LF_Resistor; Status: Preferred; TOLERANCE: 5%; WATTAGE: 1/16W; fp_ECN: 0402 SERIES_LL34.xls
R518 R522 = R: RES CHIP 33.2 1/16W +-1%(0402); CLASS: DISCRETE; CMPLS_LVL: EP; Data: CYN_LF_RL SERIES.pdf; From_pj: A06-EDISON; Lifecycle: Comp-Approve; MATERIAL: CHIP; Manuf_PN: RR0510S-33R2-FN; Manuf_name: CYNTEC CO.. LTD.; Manufacturer: CYN; Manuftr: CYN; Part_Type: *LF_Resistor; TOLERANCE: 1%; WATTAGE: 1/16W; fp_ECN: 0402 SERIES_LL34.xls; top_bot: TOP
R87 R504 R691 R775 = R: RES CHIP 1K 1/16W +-1% (0402); CLASS: DISCRETE; CMPLS_LVL: EP; Data: WTC_LF_WR SERIES.pdf; Lifecycle: Comp-Approve; MATERIAL: CHIP; Manuf_PN: RR0510S-102-FN; Manuf_name: CYNTEC CO.. LTD.; Manuftr: CYN; Part_Type: *LF_Resistor; Status: Preferred; TOLERANCE: 1%; WATTAGE: 1/16W; fp_ECN: 0402 SERIES_LL34.xls
C73 C74 C79 C80 C100 C101 C482 C495 C501 C632 = CAP_NP: CAP CHIP 0.1U 16V(10%.X7R.0402); CLASS: DISCRETE; CMPLS_LVL: EP(V1); Data: MUR_LF_CAP SERIES_1.pdf; From_pj: S5A-TRAVIS; Lifecycle: Comp-Approve; MATERIAL: X7R; Manuf_PN: WBM155R71C104K; Manuf_name: MURATA ERIE N.A. INC TAIWAN BRANCH Okayama Murata Mfg.Co..Ltd. Wakura Murata Mfg; Manufacturer: MUR; Manuftr: MUR; Part_Type: *LF_C0402; RD_CMPLS_LVL: EP(V1); ROOM: VR_P1V05_PCH; TOLERANCE: 10%; Top_bot: TOP; VOLTAGE: 16V; fp_ECN: 0402 SERIES_LL34.xls
Q5 = MOSFET_DUAL_6P: TRANS MOS 2N7002KDW(60V115MA,0.2W)SOT363; CLASS: IC; CMPLS_LVL: EP(V1); Data: PJT_2N7002KDW.pdf; From_pj: F06S-KENG-YU; Lifecycle: Comp-Approve; MATERIAL: IC; Manuf_name: PAN JIT INTERNATIONAL INC.; Manuftr: PJT; Part_Type: *LF_Semiconductor; RD_CMPLS_LVL: EP(V1)
R58 R244 R707 = R: RES CHIP 10K 1/16W +-1% (0402); CLASS: DISCRETE; CMPLS_LVL: EP; Data: WTC_LF_WR SERIES.pdf; From_pj: S82; Lifecycle: Comp-Approve; MATERIAL: CHIP; Manuf_PN: RR0510S-103-FN; Manuf_name: CYNTEC CO.. LTD.; Manuftr: CYN; Not_insert: NI; Part_Type: *LF_Resistor; Status: Preferred; TOLERANCE: 1%; WATTAGE: 1/16W; fp_ECN: 0402 SERIES_LL34.xls
R64 R846 = R: RES CHIP 200 1/16W +-1%(0402); CLASS: DISCRETE; CMPLS_LVL: EP; Data: WTC_LF_WR SERIES-4.pdf; From_pj: S79-C.Y.HUANG; Lifecycle: Comp-Approve; MATERIAL: CHIP; Manuf_PN: WR04X2000FTL; Manuf_name: WALSIN TECHNOLOGY CORPORATION; Manuftr: WTC; Part_Type: *LF_Resistor; TOLERANCE: 1%; WATTAGE: 1/16W; fp_ECN: 0402 SERIES_LL34.xls
R82 R304 R357 R358 = R: RES CHIP 75 1/16W +-1% (0402); CLASS: DISCRETE; CMPLS_LVL: EP; Data: WTC_LF_WR SERIES.pdf; From_pj: S07-CT; Lifecycle: Comp-Approve; MATERIAL: CHIP; Manuf_PN: RR0510S-750-FN; Manuf_name: CYNTEC CO.. LTD.; Manuftr: CYN; Part_Type: *LF_Resistor; Status: Normal; TOLERANCE: 1%; WATTAGE: 1/16W; fp_ECN: 0402 SERIES_LL34.xls
R182 R293 R396 R706 R720 R721 R752 R770 R781 R1208 R1414-R1416 = R: RES CHIP 10K 1/16W +-1% (0402); CLASS: DISCRETE; CMPLS_LVL: EP; Data: WTC_LF_WR SERIES.pdf; From_pj: S82; Lifecycle: Comp-Approve; MATERIAL: CHIP; Manuf_PN: RR0510S-103-FN; Manuf_name: CYNTEC CO.. LTD.; Manuftr: CYN; Part_Type: *LF_Resistor; Status: Preferred; TOLERANCE: 1%; WATTAGE: 1/16W; fp_ECN: 0402 SERIES_LL34.xls
R174 R749 R763 R764 R780 R1156 R1355 = R: RES CHIP 33.2 1/16W +-1%(0402); CLASS: DISCRETE; CMPLS_LVL: EP; Data: CYN_LF_RL SERIES.pdf; From_pj: A06-EDISON; Lifecycle: Comp-Approve; MATERIAL: CHIP; Manuf_PN: RR0510S-33R2-FN; Manuf_name: CYNTEC CO.. LTD.; Manuftr: CYN; Part_Type: *LF_Resistor; TOLERANCE: 1%; WATTAGE: 1/16W; fp_ECN: 0402 SERIES_LL34.xls
U19 U20 U32 = 74AVCH1T45GM: IC OTHER(6P) 74AVCH1T45GM(XSON); CLASS: IC; CMPLS_LVL: EP(V1); Data: NXP_74AVCH1T45GM_REV4.pdf; From_pj: F07-HENRY; Lifecycle: Comp-Approve; MATERIAL: IC; Manuf_name: NXP semiconductors; Manuftr: NXP; Part_Type: *LF_Chipset; RD_CMPLS_LVL: EP(V1); Standard: Potential
R395 = R: RES CHIP 5.1K 1/16W +-1%(0402); CLASS: DISCRETE; CMPLS_LVL: EP; Data: MAT_LF_RES SERIES.pdf; From_pj: S10-ANTONY; Lifecycle: Comp-Approve; MATERIAL: CHIP; Manuf_PN: RR0510S-512-FN; Manuf_name: CYNTEC CO.. LTD.; Manuftr: CYN; Part_Type: *LF_Resistor; Status: Normal; TOLERANCE: 1%; WATTAGE: 1/16W; fp_ECN: 0402 SERIES_LL34.xls
R842 R1158 R1175 = R: RES CHIP 22 1/16W +-1%(0402); CLASS: DISCRETE; CMPLS_LVL: EP; Data: RHT_LF_RES SERIES-2.pdf; From_pj: S75-L.A.; Lifecycle: Comp-Approve; MATERIAL: CHIP; Manuf_PN: CR0222R0F002S; Manuf_name: RTECH TECHNOLOGY CO..LTD. (Compostar); Manuftr: RHT; Part_Type: *LF_Resistor; Standard: ##; Status: Preferred; TOLERANCE: 1%; WATTAGE: 1/16W; fp_ECN: 0402 SERIES_LL34.xls
R848 = R: RES CHIP 300 1/16W +-1%(0402); CLASS: DISCRETE; CMPLS_LVL: EP; Data: TR-0306029.pdf; From_pj: S06; Lifecycle: Comp-Approve; MATERIAL: CHIP; Manuf_PN: CR02300RF002; Manuf_name: "RTECH TECHNOLOGY CO..LTD.(Compostar)"; Manuftr: RHT; Part_Type: Resistor; Status: Preferred; TOLERANCE: 1%; WATTAGE: 1/16W; fp_ECN: 0402 SERIES_LL34.xls
U42 = 74AVCH4T245GU: IC OTHER(16P) 74AVCH4T245GU(XQFN); CLASS: IC; CMPLS_LVL: EP(V1); Data: NXP_74AVCH4T245GU_REV4.pdf; From_pj: F07-HENRY; Lifecycle: Comp-Approve; MATERIAL: IC; Manuf_name: NXP semiconductors; Manuftr: NXP; Part_Type: *LF_Chipset; RD_CMPLS_LVL: EP(V1); Standard: Potential
U46 = 74AVCH8T245PW: IC OTHER(24P) 74AVCH8T245PW(TSSOP); CLASS: IC; Data: NXP_74AVCH8T245PW_REV5.pdf; From_pj: F07-HENRY; Lifecycle: Comp-Approve; MATERIAL: IC; Manuf_name: NXP semiconductors; Manuftr: NXP; Part_Type: *LF_Chipset; RD_CMPLS_LVL: EP(V1); Standard: Potential
U80 U120 = SN74LVC1G07: IC OTHER(5P)SN74LVC1G07DCKR(SOT); CLASS: IC; CMPLS_LVL: EP(V1); Data: TIC_SN74LVC1G07DCKR.pdf; From_pj: S50-STEVE; Lifecycle: Comp-Approve; MATERIAL: IC; Manuf_name: TEXAS INSTRUMENTS SUPPLY CO..; Manufacturer: TIC; Manuftr: TIC; Part_Type: *LF_Chipset; RD_CMPLS_LVL: EP(V1); Standard: Potential
R753 = R: RES CHIP 1K 1/16W +-1% (0402); CLASS: DISCRETE; CMPLS_LVL: EP; Data: WTC_LF_WR SERIES.pdf; Lifecycle: Comp-Approve; MATERIAL: CHIP; Manuf_PN: RR0510S-102-FN; Manuf_name: CYNTEC CO.. LTD.; Manuftr: CYN; Not_insert: NI; Part_Type: *LF_Resistor; Status: Preferred; TOLERANCE: 1%; WATTAGE: 1/16W; fp_ECN: 0402 SERIES_LL34.xls
R789 = R: RES CHIP 10K 1/16W +-1% (0402); CLASS: DISCRETE; CMPLS_LVL: EP; Data: WTC_LF_WR SERIES.pdf; From_pj: S82; Lifecycle: Comp-Approve; MATERIAL: CHIP; Manuf_PN: RR0510S-103-FN; Manuf_name: CYNTEC CO.. LTD.; Manufacturer: RLC; Manuftr: CYN; Part_Type: *LF_Resistor; Status: Preferred; TOLERANCE: 1%; WATTAGE: 1/16W; fp_ECN: 0402 SERIES_LL34.xls; top_bot: TOP
U55 = MX25L12835FM2I10G: IC FLASH(8P) MX25L12835FM2I-10G(SOP); CLASS: IC; CMPLS_LVL: EP(V1); Data: MAX_MX25L12835FM2I-10G.pdf; From_pj: T20-TONY; Lifecycle: Comp-Approve; MATERIAL: IC; Manuf_name: MACRONIX, INC.; Manuftr: MAX; Part_Type: *LF_Chipset; RD_CMPLS_LVL: EP(V1)
U56 = W25X80: IC SOCKET SMD 8P SPI (P1.27.H5.4); CLASS: IO; CMPLS_LVL: EU(V1); Data: WSE_X6179-1000XX.pdf; From_pj: A05-JACK; Lifecycle: Comp-Approve; MATERIAL: IO; Manuf_PN: G6179-100000; Manuf_name: WIESON ELECTRONIC CO.,LTD. (Wieson International Co., Ltd); Manuftr: WSE; Part_Type: *LF_Connector; RD_CMPLS_LVL: EU(V1); Standard: End of Design
C679 = CAP_NP: CAP CHIP 0.1U 10V(+-10%.X7R.0402); CLASS: DISCRETE; CMPLS_LVL: EP; Data: RHT_LF_CAP SERIES-1.pdf; From_pj: S82-ICE; Lifecycle: Comp-Approve; MATERIAL: X7R; Manuf_PN: GRM155R71A104K; Manuf_name: "MURATA ERIE N.A. INC TAIWAN BRANCH Okayama Murata Mfg.Co..Ltd.Wakura Murata Mfg; Manuftr: MUR; Part_Type: *LF_C0402; Standard: ##; Status: Preferred; TOLERANCE: 10%; VOLTAGE: 10V; fp_ECN: 0402 SERIES_LL34.xls
R709 R1352 = R: RES CHIP 4.7K 1/16W +-5% (0402); CLASS: DISCRETE; CMPLS_LVL: EP; Data: WTC_LF_WR SERIES.pdf; Lifecycle: Comp-Approve; MATERIAL: CHIP; Manuf_PN: RR0510S-472-JN; Manuf_name: CYNTEC CO.. LTD.; Manufacturer: CYN; Manuftr: CYN; Part_Type: *LF_Resistor; Status: Preferred; TOLERANCE: 5%; TOP_BOT: BOT; WATTAGE: 1/16W; fp_ECN: 0402 SERIES_LL34.xls
R723 R1102 = R: RES CHIP 49.9 1/16W +-1% (0402); CLASS: DISCRETE; CMPLS_LVL: EP; Data: WTC_LF_WR SERIES.pdf; Lifecycle: Comp-Approve; MATERIAL: CHIP; Manuf_PN: RR0510S-49R9-FN; Manuf_name: CYNTEC CO.. LTD.; Manufacturer: RHT; Manuftr: CYN; Part_Type: *LF_Resistor; Status: Preferred; TOLERANCE: 1%; WATTAGE: 1/16W; fp_ECN: 0402 SERIES_LL34.xls; top_bot: TOP
R791 = R: RES CHIP 1K 1/16W +-1% (0402); CLASS: DISCRETE; CMPLS_LVL: EP; Data: WTC_LF_WR SERIES.pdf; Lifecycle: Comp-Approve; MATERIAL: CHIP; Manuf_PN: RR0510S-102-FN; Manuf_name: CYNTEC CO.. LTD.; Manufacturer: CYN; Manuftr: CYN; Part_Type: *LF_Resistor; Status: Preferred; TOLERANCE: 1%; WATTAGE: 1/16W; fp_ECN: 0402 SERIES_LL34.xls
R1356 = R: RES CHIP 4.7K 1/16W +-5% (0402); CLASS: DISCRETE; CMPLS_LVL: EP; Data: WTC_LF_WR SERIES.pdf; Lifecycle: Comp-Approve; MATERIAL: CHIP; Manuf_PN: RR0510S-472-JN; Manuf_name: CYNTEC CO.. LTD.; Manuftr: CYN; Part_Type: *LF_Resistor; Status: Preferred; TOLERANCE: 5%; WATTAGE: 1/16W; fp_ECN: 0402 SERIES_LL34.xls
U87 = SN74LVC2G07DCKR: IC(6P) SN74LVC2G07DCKR(SC70-6); CLASS: IC; CMPLS_LVL: EP(V1); Data: SN74LVC2G07.pdf; From_pj: S2RS-WIN; Lifecycle: Comp-Approve; MATERIAL: IC; Manuf_name: TEXAS INSTRUMENTS SUPPLY CO..; Manuftr: TIC; Part_Type: *LF_Chipset; RD_CMPLS_LVL: EP(V1); Standard: Potential
R59 R425 R426 R739 R748 R774 R790 R1215 R1216 R1220 = R: RESISTOR CHIP 0 1/16W +-5%(0402); BOM: TI; CLASS: DISCRETE; CMPLS_LVL: EP; Data: WTC_LF_WR SERIES.pdf; Lifecycle: Comp-Approve; MATERIAL: CHIP; Manuf_PN: RR0510X-000-XN; Manuf_name: CYNTEC CO.. LTD.; Manufacturer: CYN; Manuftr: CYN; Part_Type: *LF_Resistor; Status: Preferred; TOLERANCE: 5%; WATTAGE: 1/16W; fp_ECN: 0402 SERIES_LL34.xls; top_bot: TOP
R337 R1207 = R: RES CHIP 4.7K 1/16W +-5% (0402); CLASS: DISCRETE; CMPLS_LVL: EP; Data: WTC_LF_WR SERIES.pdf; Lifecycle: Comp-Approve; MATERIAL: CHIP; Manuf_PN: RR0510S-472-JN; Manuf_name: CYNTEC CO.. LTD.; Manufacturer: RLC; Manuftr: CYN; Part_Type: *LF_Resistor; Status: Preferred; TOLERANCE: 5%; WATTAGE: 1/16W; fp_ECN: 0402 SERIES_LL34.xls; top_bot: TOP
R1248-R1250 = R: RES CHIP 4.7K 1/16W +-5% (0402); BOM: AST2300; CLASS: DISCRETE; CMPLS_LVL: EP; Data: WTC_LF_WR SERIES.pdf; Lifecycle: Comp-Approve; MATERIAL: CHIP; Manuf_PN: RR0510S-472-JN; Manuf_name: CYNTEC CO.. LTD.; Manufacturer: CYN; Manuftr: CYN; Not_insert: NI; Part_Type: *LF_Resistor; Status: Preferred; TOLERANCE: 5%; WATTAGE: 1/16W; fp_ECN: 0402 SERIES_LL34.xls
R1251 = R: RES CHIP 4.7K 1/16W +-5% (0402); BOM: AST2300; CLASS: DISCRETE; CMPLS_LVL: EP; Data: WTC_LF_WR SERIES.pdf; Lifecycle: Comp-Approve; MATERIAL: CHIP; Manuf_PN: RR0510S-472-JN; Manuf_name: CYNTEC CO.. LTD.; Manufacturer: CYN; Manuftr: CYN; Part_Type: *LF_Resistor; Status: Preferred; TOLERANCE: 5%; WATTAGE: 1/16W; fp_ECN: 0402 SERIES_LL34.xls
U74 U97 = PI3B3257: IC OTHER(16P)PI3B3257QE(QSOP); CLASS: IC; CMPLS_LVL: EP(V1); Data: PIM_PI3B3257.pdf; From_pj: S75-GARRY; Lifecycle: Comp-Approve; MATERIAL: IC; Manuf_name: PERICOM SEMICONDUCTOR CORPORAT; Manuftr: PIM; Part_Type: *LF_Chipset; RD_CMPLS_LVL: EP(V1)

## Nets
GND: C73.1 C74.1 C79.1 C80.1 C100.1 C101.1 C109.2 C117.2 C127.2 C131.2 C146.2 C162.2 C314.1 C329.2 C344.1 C365.2 C368.2 C372.1 C373.2 C374.2 C376.1 C377.2 C381.2 C382.2 C383.2 C384.2 C388.2 C389.1 C390.1 C393.2 C395.2 C396.2 C398.2 C407.2 C409.2 C414.2 C416.2 C419.2 C421.2 C425.2 C426.2 C427.2 C430.1 C431.2 C433.2 C434.2 C435.2 C439.2 C441.2 C442.2 C446.2 C482.2 C495.2 C501.1 C542.1 C632.1 C679.2 J23.1 J23.2 J23.7 J23.8 J23.13 J23.14 J23.19 J23.20 J23.25 J23.26 J23.31 J23.32 J23.37 J23.38 J23.49 J23.50 J23.59 Q5.1(S1) Q5.4(S2) R182.2 R337.1 R395.1 R753.1 R781.2 R791.1 R1207.1 R1208.2 U19.2(GND) U20.2(GND) U30.A3(VSS1) U30.A5(VSS3) U30.A6(VSS4) U30.A20(VSS0) U30.A77(VSS6) U30.AA12(VSS2) U30.AA21(VSS18) U30.AA23(VSS7) U30.AA25(VSS8) U30.AA56(VSS11) U30.AA60(VSS12) U30.AA62(VSS13) U30.AA69(VSS14) U30.AB5(VSS15) U30.AB74(VSS16) U30.AC2(VSS21) U30.AC12(VSS17) U30.AC16(VSS19) U30.AC18(VSS20) U30.AC27(VSS22) U30.AC58(VSS24) U30.AD5(VSS26) U30.AE7(VSS32) U30.AE11(VSS27) U30.AE14(VSS23) U30.AE19(VSS28) U30.AE23(VSS29) U30.AE64(VSS30) U30.AE67(VSS31) U30.AE71(VSS33) U30.AF5(VSS34) U30.AF9(VSS38) U30.AF74(VSS35) U30.AF76(VSS36) U30.AF78(VSS37) U30.AG12(VSS41) U30.AG16(VSS52) U30.AG62(VSS39) U30.AH3(VSS48) U30.AH5(VSS50) U30.AH12(VSS40) U30.AH16(VSS42) U30.AH18(VSS43) U30.AH19(VSS44) U30.AH25(VSS45) U30.AH27(VSS46) U30.AH28(VSS47) U30.AH30(VSS49) U30.AH53(VSS51) U30.AH56(VSS53) U30.AH66(VSS54) U30.AH69(VSS55) U30.AH74(VSS56) U30.AK16(VSS57) U30.AK19(VSS58) U30.AK60(VSS61) U30.AK75(VSS62) U30.AK77(VSS63) U30.AL7(VSS67) U30.AL11(VSS64) U30.AL64(VSS65) U30.AL67(VSS66) U30.AL71(VSS68) U30.AM9(VSS73) U30.AM19(VSS69) U30.AM21(VSS70) U30.AM28(VSS71) U30.AM30(VSS72) U30.AN5(VSS74) U30.AN74(VSS75) U30.AN76(VSS76) U30.AP14(VSS77) U30.AP19(VSS78) U30.AP23(VSS79) U30.AP53(VSS59) U30.AR1(VSS82) U30.AR3(VSS86) U30.AR5(VSS87) U30.AR12(VSS83) U30.AR19(VSS84) U30.AR25(VSS85) U30.AR53(VSS60) U30.AR55(VSS88) U30.AR56(VSS80) U30.AR60(VSS89) U30.AU1(VSS92) U30.AU3(VSS97) U30.AU5(VSS99) U30.AU19(VSS93) U30.AU23(VSS94) U30.AU25(VSS95) U30.AU28(VSS96) U30.AU30(VSS98) U30.AU53(VSS123) U30.AU55(VSS100) U30.AU56(VSS101) U30.AU58(VSS102) U30.AU62(VSS103) U30.AU66(VSS104) U30.AU69(VSS105) U30.AU72(VSS106) U30.AU74(VSS107) U30.AU76(VSS91) U30.AU78(VSS90) U30.AV2(VSS190) U30.AV64(VSS108) U30.AV67(VSS109) U30.AV71(VSS110) U30.AV75(VSS111) U30.AV77(VSS112) U30.AW5(VSS113) U30.AW9(VSS114) U30.B2(VSS115) U30.B48(VSS191) U30.B74(VSS10) U30.B77(VSS117) U30.B78(VSS118) U30.BA3(VSS122) U30.BA12(VSS119) U30.BA16(VSS120) U30.BA28(VSS121) U30.BA56(VSS124) U30.BB2(VSS203) U30.BB19(VSS125) U30.BB33(VSS255) U30.BB35(VSS126) U30.BD1(VSS127) U30.BD5(VSS130) U30.BD14(VSS128) U30.BD33(VSS129) U30.BE9(VSS138) U30.BE28(VSS131) U30.BE35(VSS132) U30.BE66(VSS133) U30.BE69(VSS134) U30.BE72(VSS135) U30.BE75(VSS136) U30.BE77(VSS137) U30.BF5(VSS141) U30.BF26(VSS139) U30.BF30(VSS140) U30.BF56(VSS142) U30.BF64(VSS143) U30.BF67(VSS144) U30.BF71(VSS145) U30.BF74(VSS146) U30.BF76(VSS147) U30.BF78(VSS148) U30.BG24(VSS149) U30.BG35(VSS150) U30.BG62(VSS151) U30.BG69(VSS152) U30.BH3(VSS156) U30.BH5(VSS158) U30.BH11(VSS153) U30.BH14(VSS154) U30.BH18(VSS155) U30.BH30(VSS157) U30.BH60(VSS159) U30.BH64(VSS160) U30.BH74(VSS161) U30.BJ24(VSS162) U30.BJ35(VSS163) U30.BJ58(VSS164) U30.BJ69(VSS165) U30.BK1(VSS166) U30.BK5(VSS168) U30.BK37(VSS167) U30.BK74(VSS169) U30.BL30(VSS170) U30.BL56(VSS171) U30.BL64(VSS172) U30.BM9(VSS180) U30.BM13(VSS173) U30.BM16(VSS174) U30.BM20(VSS175) U30.BM24(VSS176) U30.BM35(VSS177) U30.BM69(VSS178) U30.BM74(VSS179) U30.BN30(VSS181) U30.BN37(VSS182) U30.BN60(VSS183) U30.BN64(VSS184) U30.BN75(VSS185) U30.BN77(VSS186) U30.BP3(VSS188) U30.BP24(VSS187) U30.BP35(VSS189) U30.BP62(VSS192) U30.BP69(VSS193) U30.BP74(VSS194) U30.BR11(VSS195) U30.BR14(VSS196) U30.BR18(VSS197) U30.BR22(VSS198) U30.BR30(VSS199) U30.BR64(VSS200) U30.BT24(VSS201) U30.BT35(VSS202) U30.BT56(VSS204) U30.BT69(VSS205) U30.BT74(VSS206) U30.BU2(VSS207) U30.BU4(VSS210) U30.BU30(VSS208) U30.BU37(VSS209) U30.BU64(VSS211) U30.BV9(VSS218) U30.BV13(VSS212) U30.BV24(VSS213) U30.BV35(VSS214) U30.BV58(VSS215) U30.BV62(VSS216) U30.BV69(VSS217) U30.BW5(VSS229) U30.BW7(VSS236) U30.BW11(VSS219) U30.BW14(VSS220) U30.BW30(VSS221) U30.BW39(VSS222) U30.BW40(VSS223) U30.BW42(VSS224) U30.BW43(VSS225) U30.BW45(VSS226) U30.BW47(VSS227) U30.BW49(VSS228) U30.BW50(VSS230) U30.BW52(VSS231) U30.BW54(VSS232) U30.BW55(VSS233) U30.BW60(VSS234) U30.BW64(VSS235) U30.BW74(VSS237) U30.BY16(VSS238) U30.BY20(VSS239) U30.BY24(VSS240) U30.BY28(VSS241) U30.BY35(VSS242) U30.BY39(VSS243) U30.BY43(VSS244) U30.BY54(VSS245) U30.BY58(VSS246) U30.BY62(VSS247) U30.BY66(VSS248) U30.BY69(VSS249) U30.BY72(VSS250) U30.C1(VSS251) U30.C2(VSS252) U30.C20(VSS253) U30.C77(VSS256) U30.C78(VSS257) U30.CA5(VSS267) U30.CA11(VSS258) U30.CA18(VSS259) U30.CA22(VSS260) U30.CA26(VSS261) U30.CA30(VSS262) U30.CA41(VSS263) U30.CA45(VSS264) U30.CA46(VSS265) U30.CA49(VSS266) U30.CA51(VSS268) U30.CA52(VSS269) U30.CA56(VSS270) U30.CA60(VSS271) U30.CA64(VSS272) U30.CA67(VSS273) U30.CA71(VSS274) U30.CA74(VSS275) U30.CA76(VSS276) U30.CA78(VSS277) U30.CB16(VSS278) U30.CB32(VSS279) U30.F3(VSS9) U30.F72(VSS116) U30.F78(VSS25) U30.L3(VSS254) U30.L69(VSS5) U30.R46(VSS81) U32.2(GND) U32.5(DIR) U42.1(1OE_N) U42.4(1DIR) U42.5(2DIR) U42.10(GND_1) U42.11(GND_2) U42.16(2OE_N) U46.2(DIR) U46.11(GND1) U46.12(GND2) U46.13(GND3) U46.22(OE#) U55.4(GND) U56.4(Vss) U74.8(GND) U80.3(GND) U87.2(GND) U97.8(GND) U120.3(GND) ; also on sheet 1 2 3 4 11 12 13 14 15 16 17 18 19 20 22 23 24 25 26 27 28 31 32 41 42 45 46 47 48 49 50 51 60 61 62 63 64 65 66 67 68 69 70 71 72 73 74 75 77 79 81 82 83 84 86 87 88 92
P1V05_COMBINED: C79.2 C80.2 C100.2 C127.1 C146.1 C395.1 C409.1 C414.1 R82.1 R244.1 R304.1 R357.1 R358.1 R360.2 R396.1 R768.2 U19.1(VCC_A) U19.5(DIR) U20.1(VCC_A) U20.5(DIR) U30.AC53(VCCIOIN1) U30.AC55(VCCIOIN0) U30.AH55(VCCIOIN3) U30.AK53(VCCIOIN5) U30.AK55(VCCIOIN2) U30.AM53(VCCIOIN4) U30.AP18(VCCIOIN6) U30.AP21(VCCIOIN7) U30.AR18(VCCIOIN8) U30.AR21(VCCIOIN9) U30.AR23(VCCIOIN10) U32.1(VCC_A) U42.2(VCC_B) U46.23(VCCB2) U46.24(VCCB1) ; also on sheet 1 3 4 16 18 19 41 42 45 47 48 50 51 63 71 74 75 79 84 92 94
P1V05_PCH: C329.1 C344.2 C381.1 C384.1 C393.1 C398.1 C416.1 C419.1 C421.1 C425.1 C426.1 C427.1 C431.1 C433.1 C434.1 C435.1 C439.1 U30.AC21(VCCCLK4) U30.AC23(VCCCLK7) U30.AC25(VCCCLK6) U30.AE21(VCCCLK5) U30.AE25(VCCCLK3) U30.AG23(VCCCLK1) U30.AG25(VCCCLK0) U30.AG27(VCCIO6) U30.AH21(VCCIO10) U30.AH23(VCCCLK2) U30.AK18(VCCIO9) U30.AK21(VCC5) U30.AK23(VCC4) U30.AK25(VCC3) U30.AK27(VCCIO5) U30.AM14(VCCUSBPLL) U30.AM16(VCCIO8) U30.AM18(VCCIO7) U30.AM23(VCC2) U30.AM25(VCC1) U30.AM27(VCCIO4) U30.AP25(VCC0) U30.AP27(VCCIO3) U30.AR27(VCCIO2) U30.AU27(VCCIO1) U30.AW27(VCCIO0) U30.BB25(P1V05_PROC_IO) ; also on sheet 50 51 63 67 74 84
P1V5_PCH: U30.AC28(VCCVRM0) U30.AC30(VCCVRM7) U30.AE28(VCCVRM4) U30.AE30(VCCVRM3) U30.AG19(VCCADAC1_5) U30.AK28(VCCVRM2) U30.AK30(VCCVRM1) U30.AW28(VCCVRM9) U30.AW30(VCCVRM8) U30.BA30(VCCVRM5) U30.BB30(VCCVRM6) ; also on sheet 31 46 47 49 94
P3V3: C73.2 C131.1 C373.1 C374.1 C377.1 C396.1 C407.1 C441.1 C442.1 C446.1 R58.1 R706.1 R707.1 R720.1 R721.1 U19.6(VCC_B) U30.AC14(VCCCLK3_35) U30.AC19(VCCADACBG3_3) U30.AE12(VCCCLK3_34) U30.AE16(VCCCLK3_30) U30.AE18(VCCCLK3_31) U30.AG14(VCCCLK3_33) U30.AG18(VCC3_36) U30.AG28(VCC3_35) U30.AG30(VCC3_34) U30.AH14(VCCCLK3_32) U30.AM12(VCC3_33) U30.AU12(VCC3_32) U30.AW25(VCC3_31) U30.BA25(VCC3_30) U42.3(VCC_A) ; also on sheet 4 19 20 32 41 42 46 47 49 50 63 67 74 77 81
P3V3_STBY: C74.2 C101.2 C109.1 C368.1 C382.1 C383.1 C388.1 C482.1 C495.1 C501.2 C542.2 C632.2 C679.1 R293.2 R504.1 R709.1 R752.2 R770.2 R789.1 R1248.1 R1249.1 R1250.1 R1251.1 R1352.1 R1356.2 R1414.2 R1415.2 R1416.2 U20.6(VCC_B) U30.AP12(VCCSUS3_34) U30.AP16(VCCSUS3_31) U30.AR14(VCCSUS3_30) U30.AR16(VCCSUS3_37) U30.AR28(VCCSUS3_33) U30.AR30(VCCSUS3_32) U30.AU18(VCCSUS3_35) U30.AW18(VCCSUS3_36) U30.AW23(VCCSUS3_38) U32.6(VCC_B) U46.1(VCCA) U55.8(VCC) U56.8(Vcc) U74.16(VCC) U80.5(VCC) U87.5(VCC) U97.16(VCC) U120.5(VCC) ; also on sheet 3 4 13 14 16 18 19 20 22 24 25 26 27 28 31 32 41 62 63 64 65 67 68 69 70 71 72 73 74 75 77 79 81 82 84 86 87 88 92
P3V_BAT: U30.AW14(VCCRTC) ; also on sheet 13 18 41 63 72
A_VCCCORE_1P05_SENSE: C314.2 U30.BT5(VCC_SENSE)
A_VCCDSW_1P05: C372.2 U30.AU21(DCPSUSBYP1) U30.AW21(DCPSUSBYP0)
A_VCCRTCEXT: C365.1 U30.AW16(DCPRTC)
A_VCCSST_1P5: C376.2 U30.AW19(DCPSST)
A_VCCSUS_1P05: C390.2 U30.AU16(DCPSUS1)
A_VCCUSB3SUS_1P05: C389.2 U30.AP28(DCPSUS3_1) U30.AP30(DCPSUS3_0)
BIOS_DIS0_BUF_N: R337.2 U74.1(S) ; also on sheet 82
CLK_100M_XDP_R_DN: J23.42 ; also on sheet 49
CLK_100M_XDP_R_DP: J23.40 ; also on sheet 49
ERROR_BDE_0: R357.2 U42.15(1B1) ; also on sheet 47
ERROR_BDE_1: R358.2 U42.14(1B2) ; also on sheet 47
ERROR_BDE_2: R304.2 U42.12(2B2) ; also on sheet 47
FM_BDXDE_CATERR_LVT3_N: R706.2 U42.8(2A1) ; also on sheet 47 64 72
FM_BDXDE_ERR0_LVT3_N: R720.2 U42.6(1A1) ; also on sheet 47 64 72
FM_BDXDE_ERR1_LVT3_N: R721.2 U42.7(1A2) ; also on sheet 47 64 72
FM_BDXDE_ERR2_LVT3_N: R707.2 U42.9(2A2) ; also on sheet 64 72
FM_BDXDE_RESET_N: R395.2 R691.2 U46.16(B6) ; also on sheet 47
FM_BDXDE_THERMTRIP_N: U46.19(B3) ; also on sheet 47 63
FM_CPLD_BDXDE_RESET_N: R1175.2 ; also on sheet 64
FM_CPLD_BDXDE_RESET_N_R: R1175.1 U46.8(A6)
FM_CPLD_BDXDE_THERMTRIP_N: U46.5(A3) ; also on sheet 64 65 72
FM_CPLD_FIVR_FAULT: U46.10(A8) ; also on sheet 64 72
FM_CPLD_PCIE_RESET_N: R791.2 U87.1(1A) U87.3(2A) U120.2(A) ; also on sheet 64
FM_CPU2PCH_THROT: R87.2 ; also on sheet 42 47
FM_CPU2PCH_THROT_LVT3: R58.2 R846.1 ; also on sheet 47
FM_CPU2PCH_THROT_R: R87.1 U19.3(A)
FM_CPU2PCH_THROT_R_LVT3: R846.2 U19.4(B)
FM_FAST_PROCHOT_BMC_N: R64.1 ; also on sheet 71
FM_FAST_PROCHOT_D1_N: Q5.5(G2) Q5.6(D1) R504.2
FM_FAST_PROCHOT_N: Q5.2(G1) ; also on sheet 14 71
FM_FAST_PROCHOT_N_R_LVT: R64.2 U20.4(B)
FM_PCH_HOT_LVT3_N: R848.2 ; also on sheet 64 71
FM_PCH_HOT_LVT3_R_N: R848.1 U46.4(A2)
H_BDE_CATERR_GTL_N: U42.13(2B1) ; also on sheet 47
H_BDXDE_FIVR_FAULT: R244.2 U46.14(B8) ; also on sheet 47
H_PROCHOT_CO_N: Q5.3(D2) R82.2 U20.3(A) ; also on sheet 47
PCHHOT_CPU_N: U46.20(B2) ; also on sheet 18 47
PD_SW0_OE_N: R781.1 U74.15(E#)
PD_SW1_OE_N: R1208.1 U97.15(E#)
PLTRST_I210_R_N: R723.1 U87.6(1Y)
PWR_BTN_XDP: J23.41 ; also on sheet 16 69
PWRGD_BDXDE_LAN: R182.1 R412.1 R1156.1 ; also on sheet 47
PWRGD_BDXDE_LAN_R: R1156.2 U32.3(A)
PWRGD_CPLD_BDXDE_LAN: U32.4(B) ; also on sheet 14
PWRGD_CPU: R408.1 U46.21(B1) ; also on sheet 18 47 63
PWRGD_CPU0_CPLD: R842.2 ; also on sheet 64 71
PWRGD_CPU0_R_CPLD: R842.1 U46.3(A1)
RST_BTN_XDP: J23.48 ; also on sheet 16 69
RST_PLTRST_BMC_N: R1102.2 R1352.2 ; also on sheet 72
RST_PLTRST_BMC_R_N: R1102.1 U87.4(2Y)
RST_PLTRST_COME_BUF_N: R1355.1 U120.4(Y)
RST_PLTRST_COME_N: R1355.2 R1356.1 ; also on sheet 13
RST_PLTRST_I210_N: R709.2 R723.2 ; also on sheet 87
SMB_HOST_XDP_CLK: R518.1 ; also on sheet 18 62 71 73
SMB_HOST_XDP_DAT: R522.1 ; also on sheet 18 62 71 73
SMB_XDP_3V3_CLK: J23.53 R518.2
SMB_XDP_3V3_DAT: J23.51 R522.2
SPI_BDE_CLK: R763.2 ; also on sheet 47
SPI_BDE_CLK_R1: R763.1 U74.7(YB)
SPI_BDE_CS0_N: R749.2 ; also on sheet 47
SPI_BDE_CS0_R1_N: R749.1 U74.4(YA)
SPI_BDE_HOLD_IO3: R789.2 U55.7(RESET#_SIO3) U56.7(~{HOLD}) ; also on sheet 47
SPI_BDE_MISO: R771.2 ; also on sheet 47 62
SPI_BDE_MISO_R1: R771.1 U74.12(YD)
SPI_BDE_MOSI: R764.2 ; also on sheet 47
SPI_BDE_MOSI_R1: R764.1 U74.9(YC)
SPI_BDE_SOC_CLK: R1209.2 R1414.1 U55.6(SCLK) U56.6(SCK)
SPI_BDE_SOC_CLK_R1: R1209.1 U97.7(YB)
SPI_BDE_SOC_CS0_N: R770.1 R1218.2 U55.1(CS#) U56.1(~{CS})
SPI_BDE_SOC_CS0_N_R1: R1218.1 U97.4(YA)
SPI_BDE_SOC_MISO: R780.1 R1214.2 R1416.1
SPI_BDE_SOC_MISO_R1: R1214.1 U97.12(YD)
SPI_BDE_SOC_MOSI: R1211.2 R1415.1 U55.5(SI_SIO0) U56.5(SI)
SPI_BDE_SOC_MOSI_R1: R1211.1 U97.9(YC)
SPI_BDE_SOC_R_MISO: R780.2 U55.2(SO_SIO1) U56.2(SO)
SPI_BDE_WP_IO2: R752.1 R753.2 U55.3(WP#_SIO2) U56.3(~{WP}) ; also on sheet 47
SPI_BMC_PCH_CLK: R1215.1 ; also on sheet 71
SPI_BMC_PCH_CLK_R: R1215.2 U97.6(B1)
SPI_BMC_PCH_CS0_N: R1216.1 ; also on sheet 71
SPI_BMC_PCH_CS0_R_N: R1216.2 U97.3(A1)
SPI_BMC_PCH_MISO: R1210.1 ; also on sheet 71
SPI_BMC_PCH_MISO_R: R1210.2 U97.13(D1)
SPI_BMC_PCH_MOSI: R1220.1 ; also on sheet 71
SPI_BMC_PCH_MOSI_R: R1220.2 U97.10(C1)
SPI_COME_CLK: R426.1 R1250.2 ; also on sheet 13
SPI_COME_CLK_R1: R426.2 U74.6(B1)
SPI_COME_CS0_N: R739.1 R1251.2 ; also on sheet 13
SPI_COME_CS0_N_R1: R739.2 U74.3(A1)
SPI_COME_MISO: R59.1 R1248.2 ; also on sheet 13
SPI_COME_MISO_R1: R59.2 U74.13(D1)
SPI_COME_MOSI: R425.1 R1249.2 ; also on sheet 13
SPI_COME_MOSI_R1: R425.2 U74.10(C1)
SPI_SOC_CLK: R748.1 R1212.1
SPI_SOC_CLK_R1: R748.2 U74.5(B0)
SPI_SOC_CLK_R2: R1212.2 U97.5(B0)
SPI_SOC_CS0_N: R730.1 R1213.1
SPI_SOC_CS0_R1_N: R730.2 U74.2(A0)
SPI_SOC_CS0_R2_N: R1213.2 U97.2(A0)
SPI_SOC_MISO: R790.1 R1217.1
SPI_SOC_MISO_R: R790.2 U74.14(D0)
SPI_SOC_MISO_R2: R1217.2 U97.14(D0)
SPI_SOC_MOSI: R774.1 R1219.1
SPI_SOC_MOSI_R1: R774.2 U74.11(C0)
SPI_SOC_MOSI_R2: R1219.2 U97.11(C0)
SPI_SW_SELECT: R1207.2 U97.1(S) ; also on sheet 71
TP_74AVCH_A5_1: U46.7(A5)
TP_74AVCH_A7: U46.9(A7)
TP_74AVCH_B5_1: U46.17(B5)
TP_74AVCH_B7_1: U46.15(B7)
TP_VCCDUSBSUS_1P05: C430.2 U30.AK14(DCPSUS2)
TP_VCCSCSUS_VSENSE: U30.AR76(VCCSCSUS_SENSE)
TP_VSS_VCCSCSUS_SENSE: U30.AR74(VSS_VCCSCSUS_SENSE)
TP_XDP0_TCK1: J23.55
TP_XDP_CPU_OBSDATA_C0: J23.10
TP_XDP_CPU_OBSDATA_C1: J23.12
TP_XDP_CPU_OBSDATA_C2: J23.16
TP_XDP_CPU_OBSDATA_C3: J23.18
TP_XDP_CPU_OBSDATA_D0: J23.28
TP_XDP_CPU_OBSDATA_D1: J23.30
TP_XDP_CPU_OBSDATA_D2: J23.34
TP_XDP_CPU_OBSDATA_D3: J23.36
TP_XDP_CPU_OBSFN_C0: J23.4
TP_XDP_CPU_OBSFN_C1: J23.6
TP_XDP_CPU_OBSFN_D0: J23.22
TP_XDP_CPU_OBSFN_D1: J23.24
TP_XDP_CPUOBSDATA_B0: J23.27
TP_XDP_CPUOBSDATA_B1: J23.29
TP_XDP_CPUOBSDATA_B2: J23.33
TP_XDP_CPUOBSDATA_B3: J23.35
VSENSE_P1V05_COMBINED_N: U30.AP77(VSS_VCCGBE_SENSE) ; also on sheet 3
VSENSE_P1V05_COMBINED_P: U30.AR78(VCCGBE_SENSE) ; also on sheet 3
VSENSE_PVCCIN_N: U30.AT75(VSS_VCCIN_SENSE) ; also on sheet 3
VSENSE_PVCCIN_P: U30.AT77(VCCIN_SENSE) ; also on sheet 3
WAKE_N_R: R174.2 ; also on sheet 47
WAKE_PCH_BUF_N_R: R174.1 R293.1 U80.4(Y)
WAKE_PCH_N: R1158.2 U80.2(A)
WAKE_PCH_N_R: R1158.1 U46.6(A4)
WAKELAN_N: R396.2 U46.18(B4) ; also on sheet 47
XDP_BDE_PRDY_N: J23.5 ; also on sheet 16 48
XDP_BDE_PREQ_N: J23.3 ; also on sheet 16 48
XDP_BDE_TCK: J23.57 ; also on sheet 48
XDP_BDE_TDI: R1421.2 ; also on sheet 16 48
XDP_BDE_TDI_R: J23.56 R1421.1
XDP_BDE_TDO: J23.52 ; also on sheet 16 48
XDP_BDE_TMS: J23.58 ; also on sheet 16 48
XDP_BDE_TRST_N: J23.54 ; also on sheet 16 48
XDP_CPU_OBSDATA_A_MBP2_N: J23.9 ; also on sheet 16 48
XDP_CPU_OBSDATA_A_MBP3_N: J23.11 ; also on sheet 16 48
XDP_CPU_OBSDATA_A_MBP4_N: J23.15 ; also on sheet 16 48
XDP_CPU_OBSDATA_A_MBP5_N: J23.17 ; also on sheet 16 48
XDP_CPU_OBSFN_B_MBP6_N: J23.21 ; also on sheet 16 48
XDP_CPU_OBSFN_B_MBP7_N: J23.23 ; also on sheet 16 48
XDP_CPU_PWR_DEBUG_N: J23.45 ; also on sheet 16 48
XDP_CPU_PWRGD: J23.39 R775.2
XDP_CPU_PWRGD_R: R408.2 R412.2 R775.1
XDP_CPU_RESET: J23.46 R691.1
XDP_CPU_SYSPWROK: J23.47 ; also on sheet 14 16 47 71
XDP_CPU_VCCOBS_AB: C162.1 J23.43 R768.1
XDP_CPU_VCCOBS_CD: C117.1 J23.44 R360.1
XDP_PRESENT_N: J23.60 ; also on sheet 16 48

Not connected (* = marked no-connect by the designer): U80 1(NC)*; U120 1(NC)*

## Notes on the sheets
sheet 52
- VCCDUSBSUS_1P05 BACK SIDE CAP
- VCCUSB3SUS_1P05 BOARD CAP
- VCCSUS_1P05 BACK SIDE CAP
- VCCUSB3SUS_1P05 BACK SIDE CAP
- BDX-DE POWER_2
sheet 53
- BDX-DE GND_1
sheet 54
- CPU XDP
- CPU XDP_1
sheet 55
- Need check the direction.
- ERROR CNTL 1
sheet 56
- Reserve the de-pop resistor.
  Follow CRB
- ERROR CNTL 2
sheet 57
- CAD Note:
  THIS PART WILL CO-LAY WITH SOCKET
  USE ALT SYMBOL ASSOCIATED WITH SOCKET FOOTPRINT
- CPU SPI
sheet 58
- PLTRST_BUFFER
sheet 59
- Channel 0 is to MODULE ROM
- Channel 1 is to CARRIER ROM
- Channel 0 FROM BDE
- Channel 1 FROM BRIDGE IC
- To BDE FLASH
- SPI MUX
